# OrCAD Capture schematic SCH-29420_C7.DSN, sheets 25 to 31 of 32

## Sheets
25 P22_HDMI_RX_TX: size A2
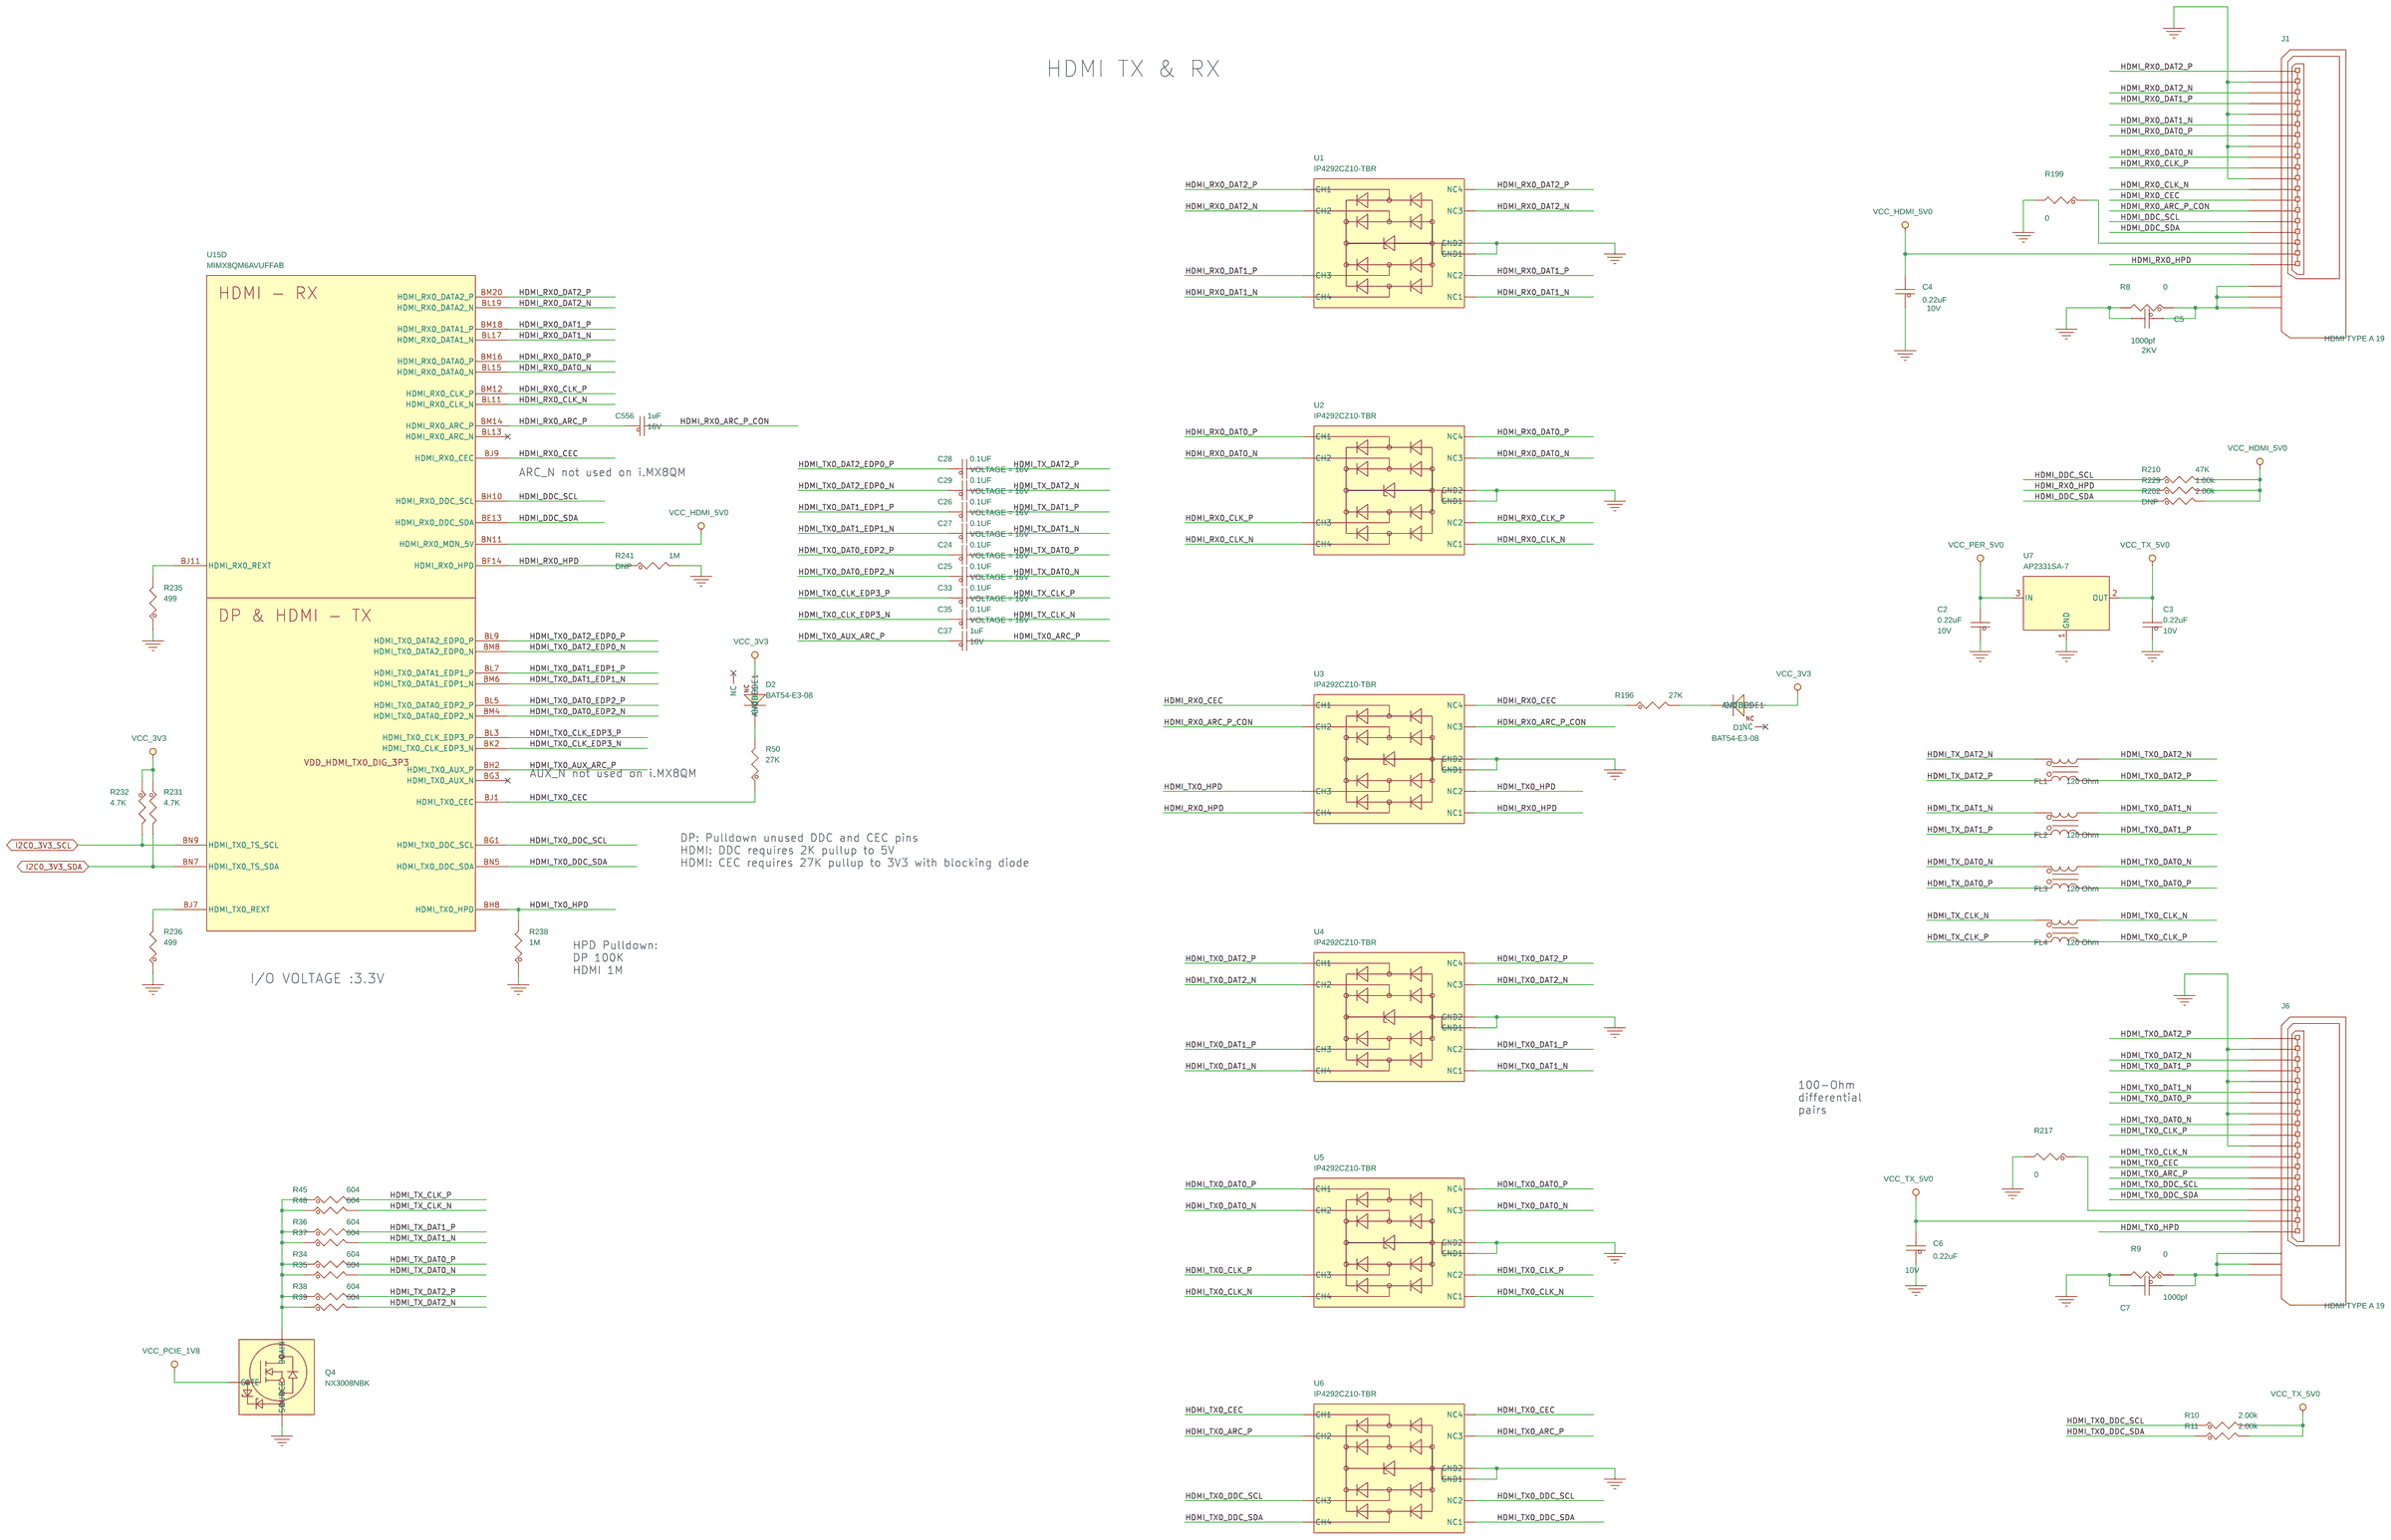
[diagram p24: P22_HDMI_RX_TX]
26 P25_WIFI_BLUETOOTH: size A2
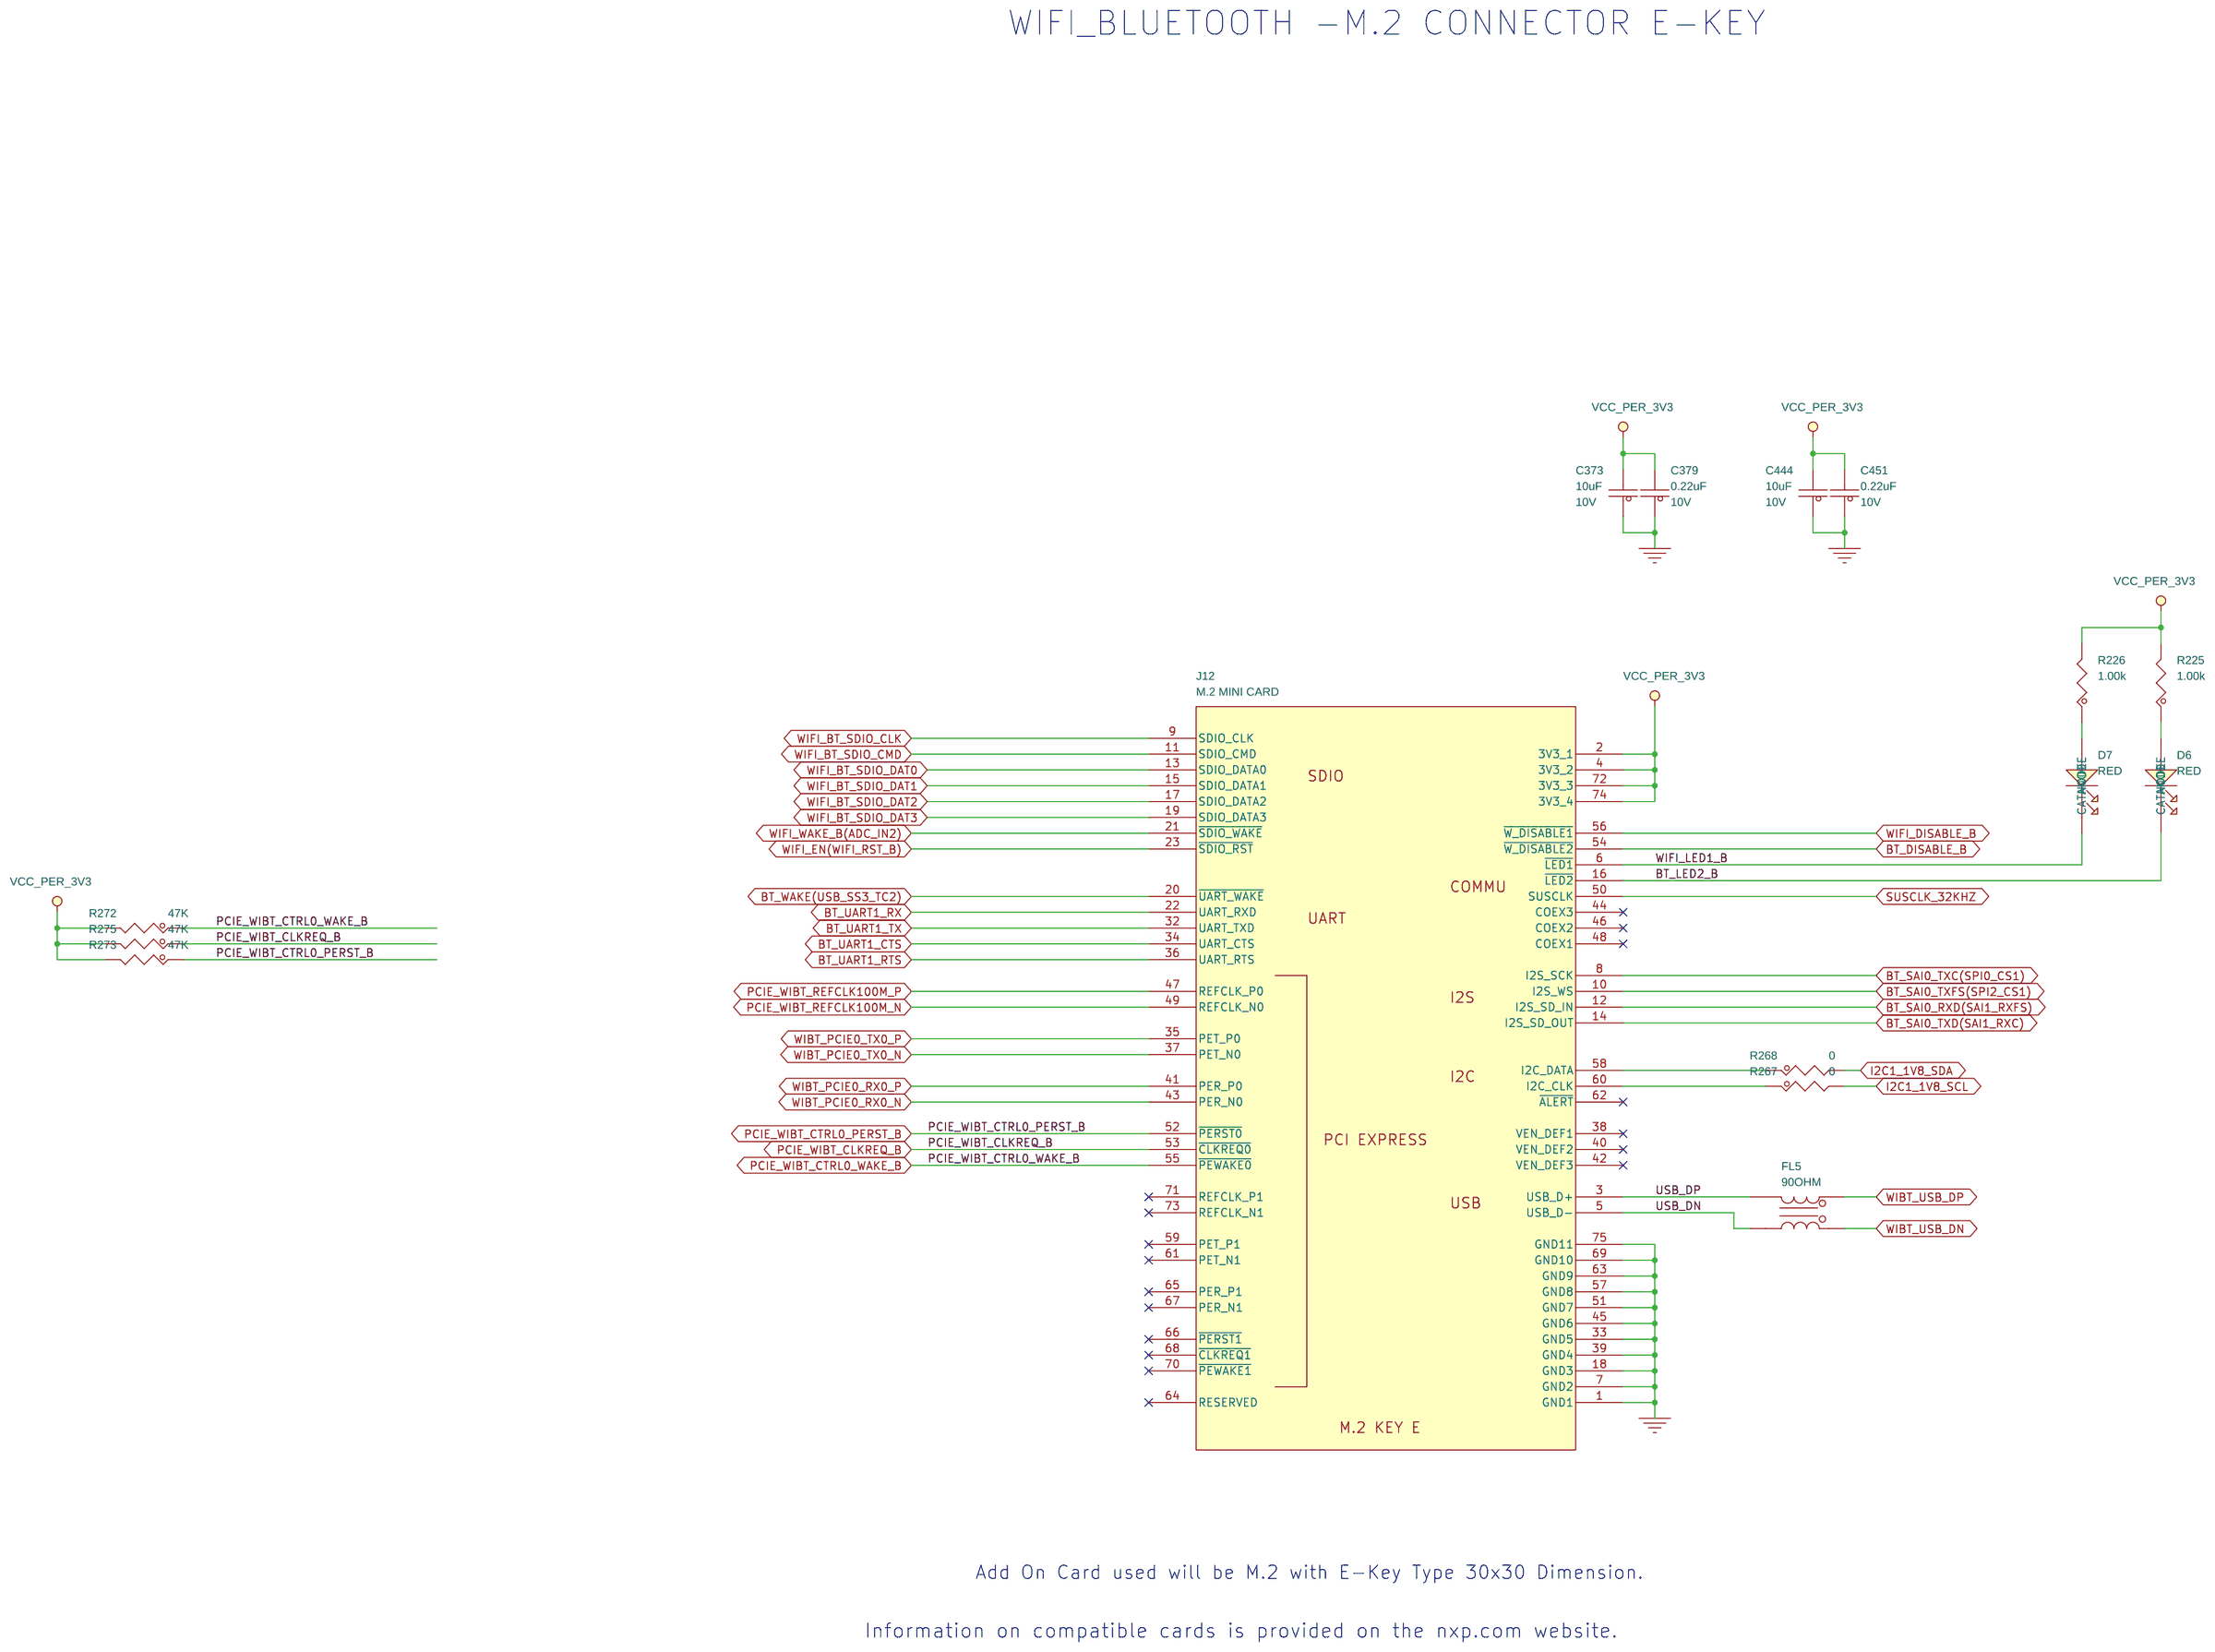
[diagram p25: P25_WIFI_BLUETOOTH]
27 P24_AUDIO CODEC_WM8960: size A2
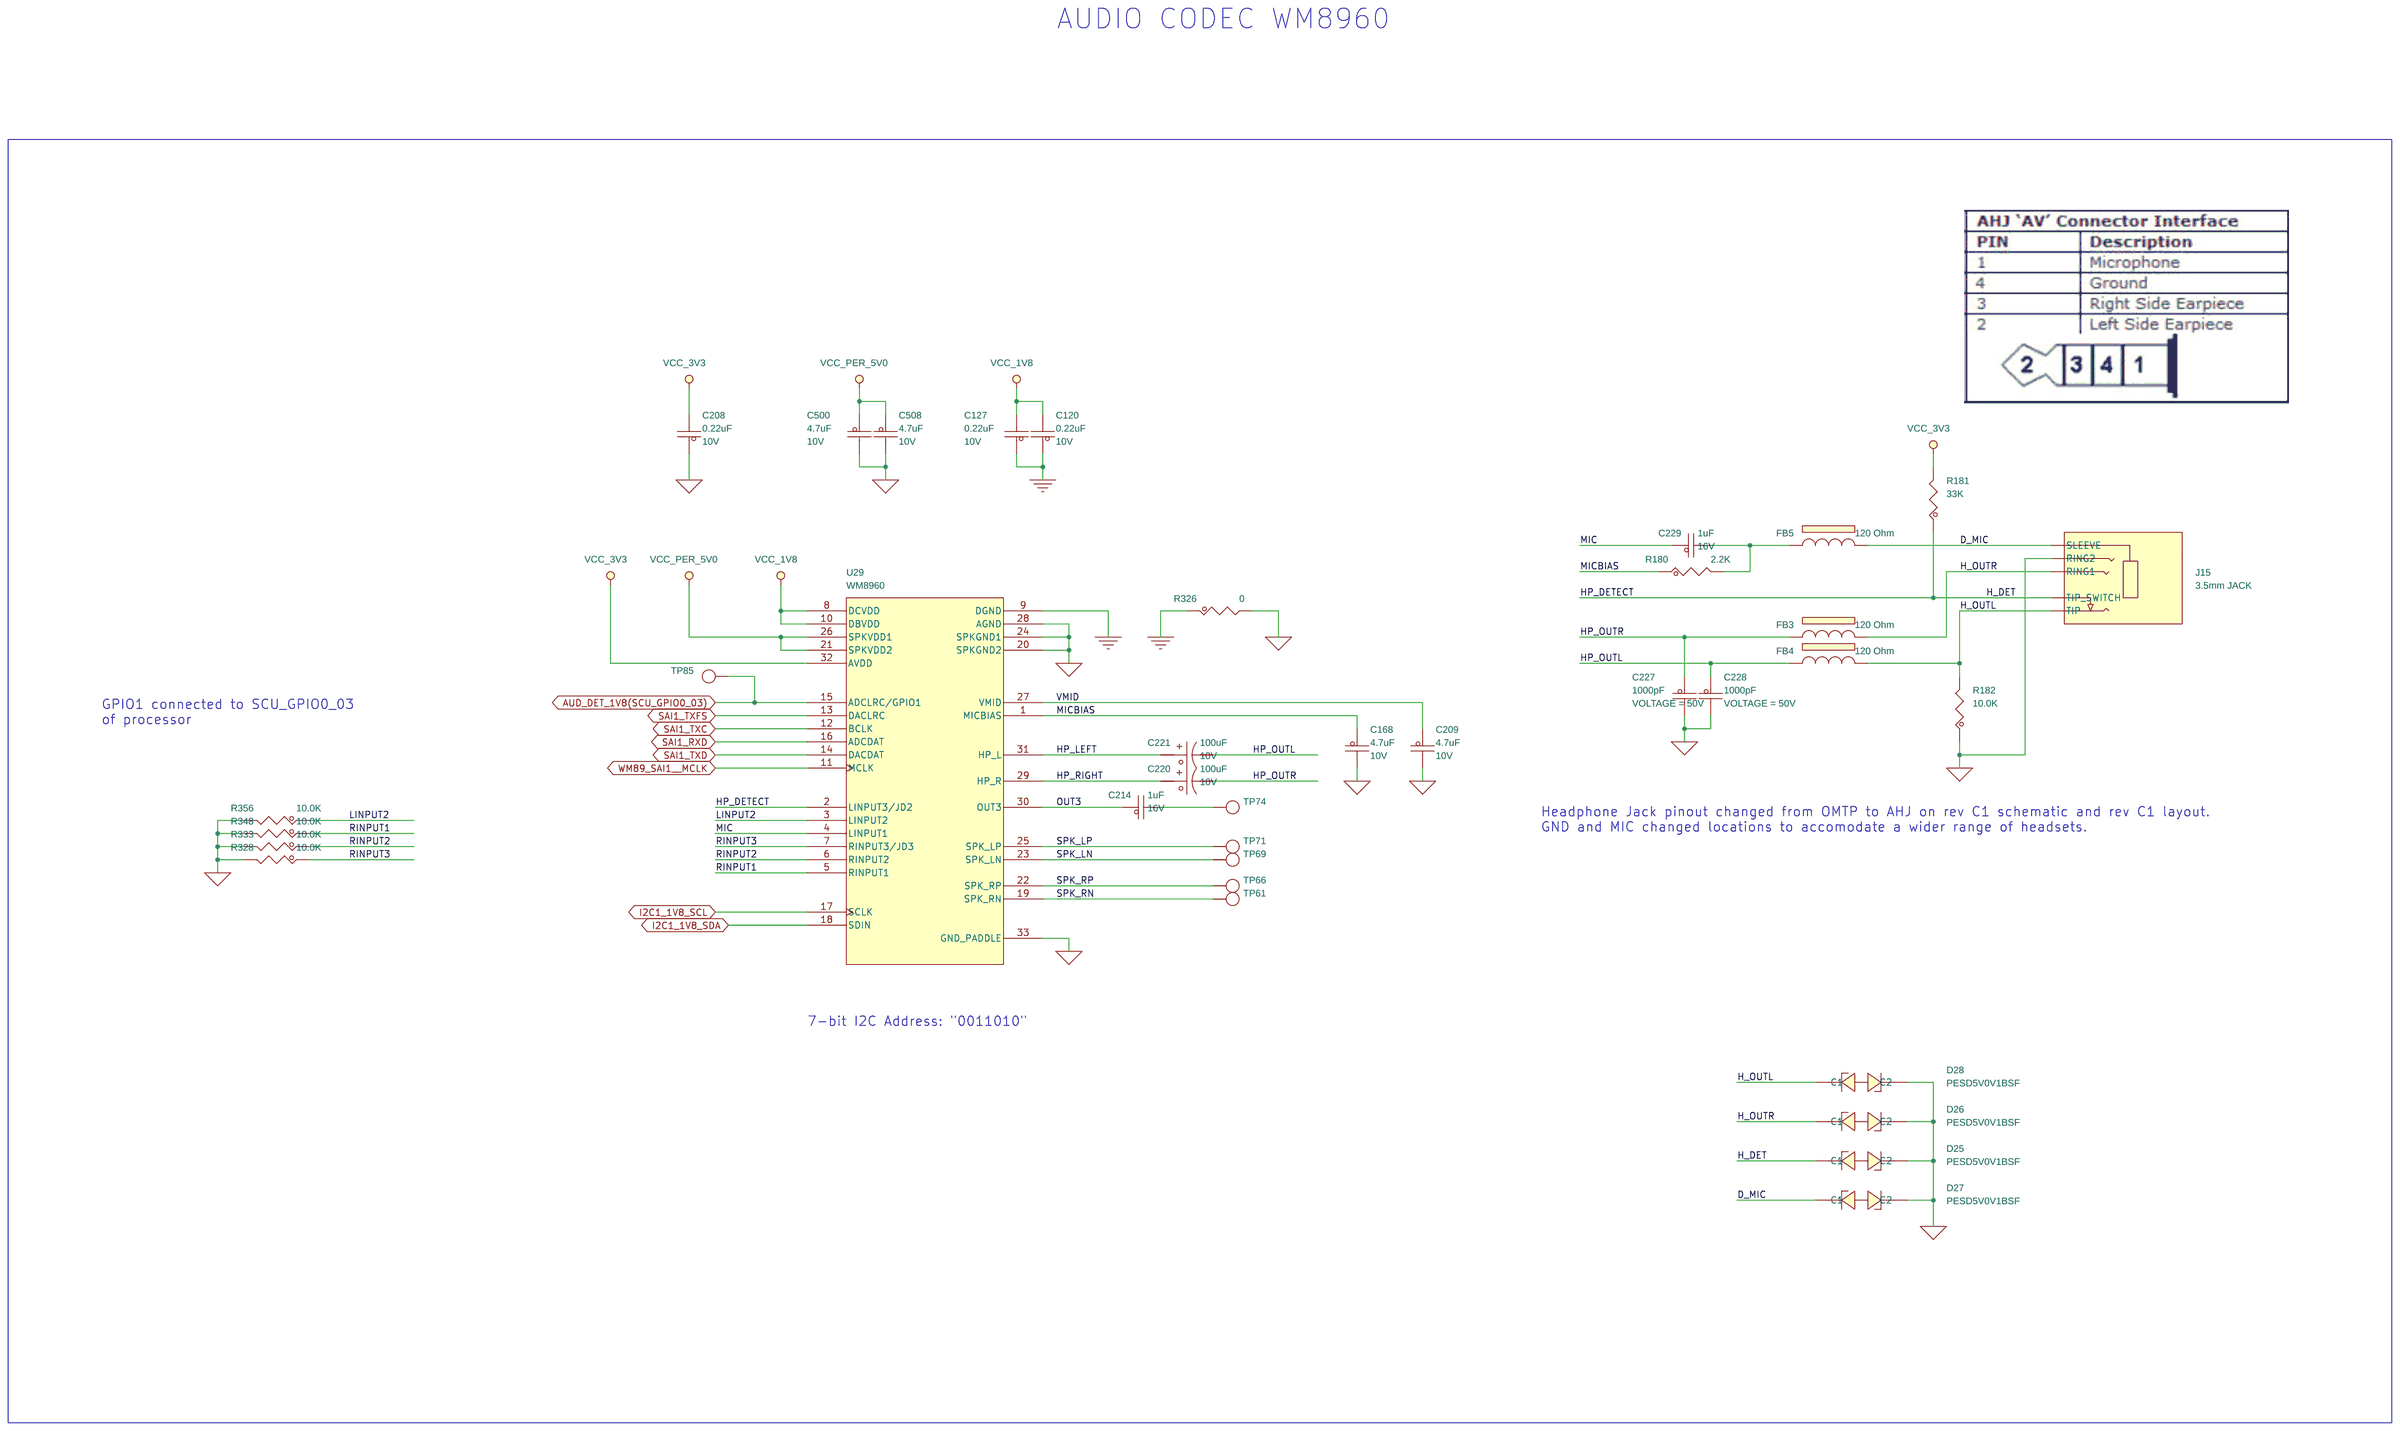
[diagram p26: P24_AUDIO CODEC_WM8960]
28 P26_SENSORS: size A2
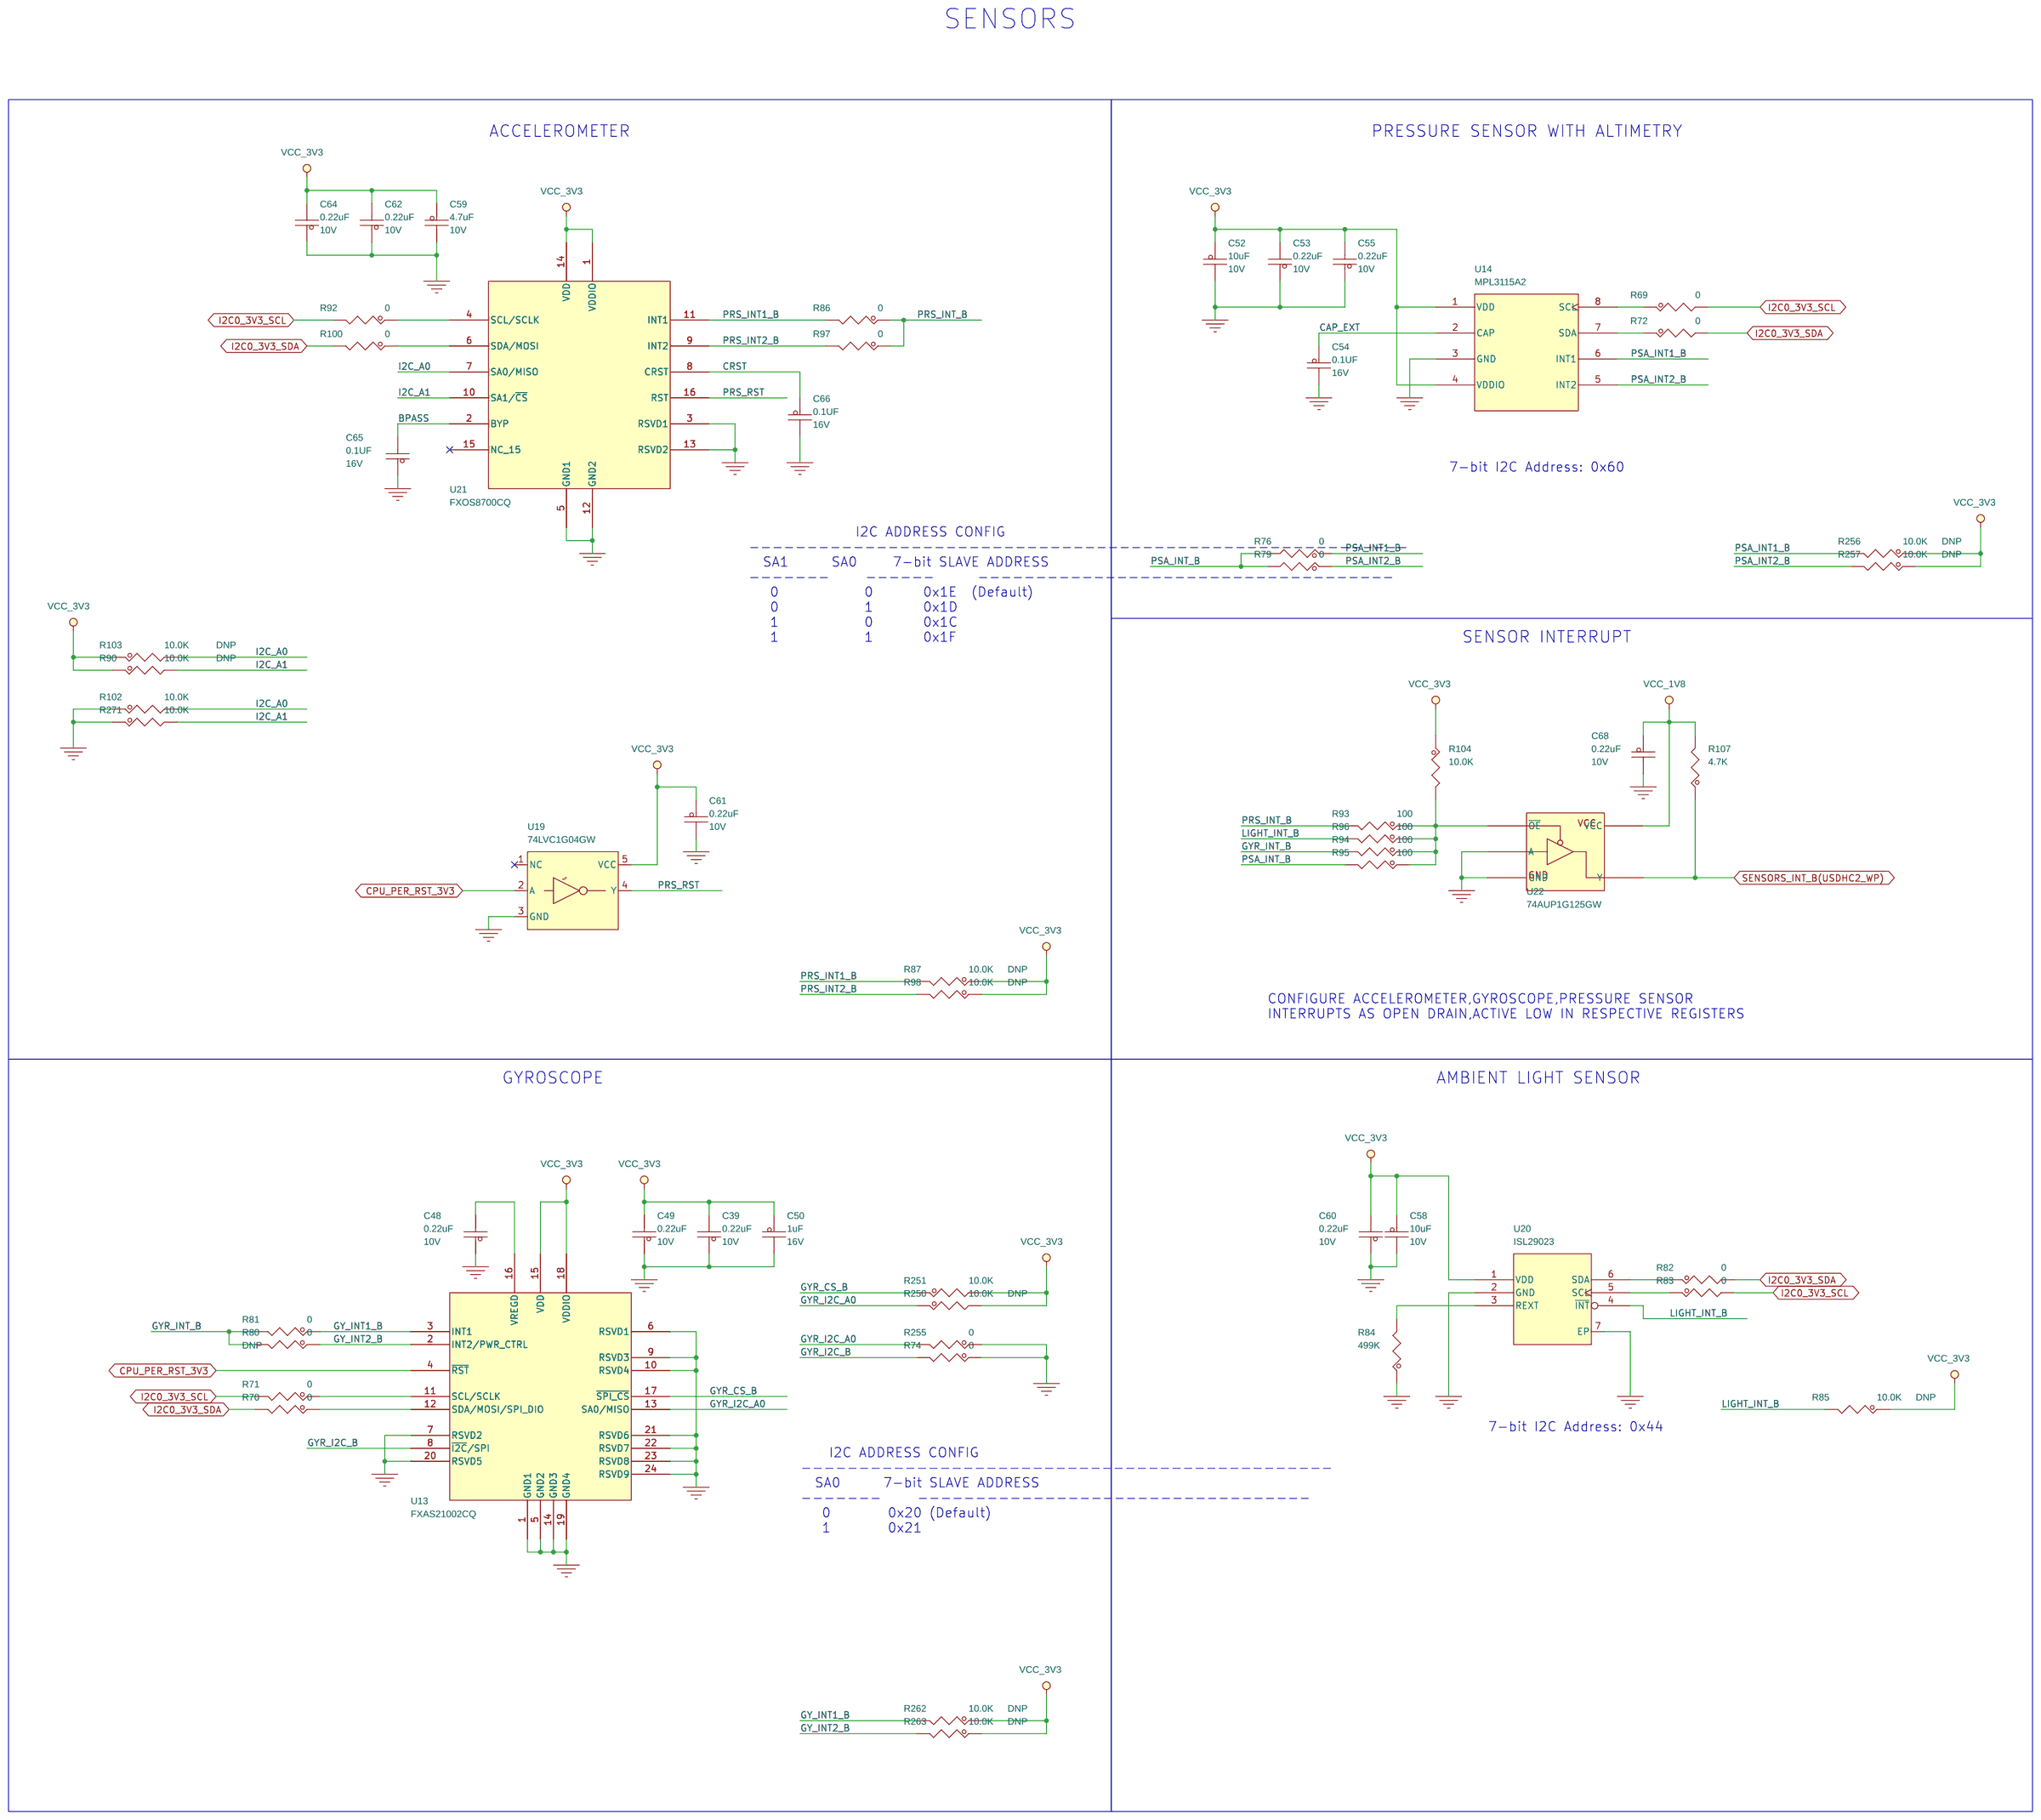
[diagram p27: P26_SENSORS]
29 P27_LVDS_CONNECTORS: size A2
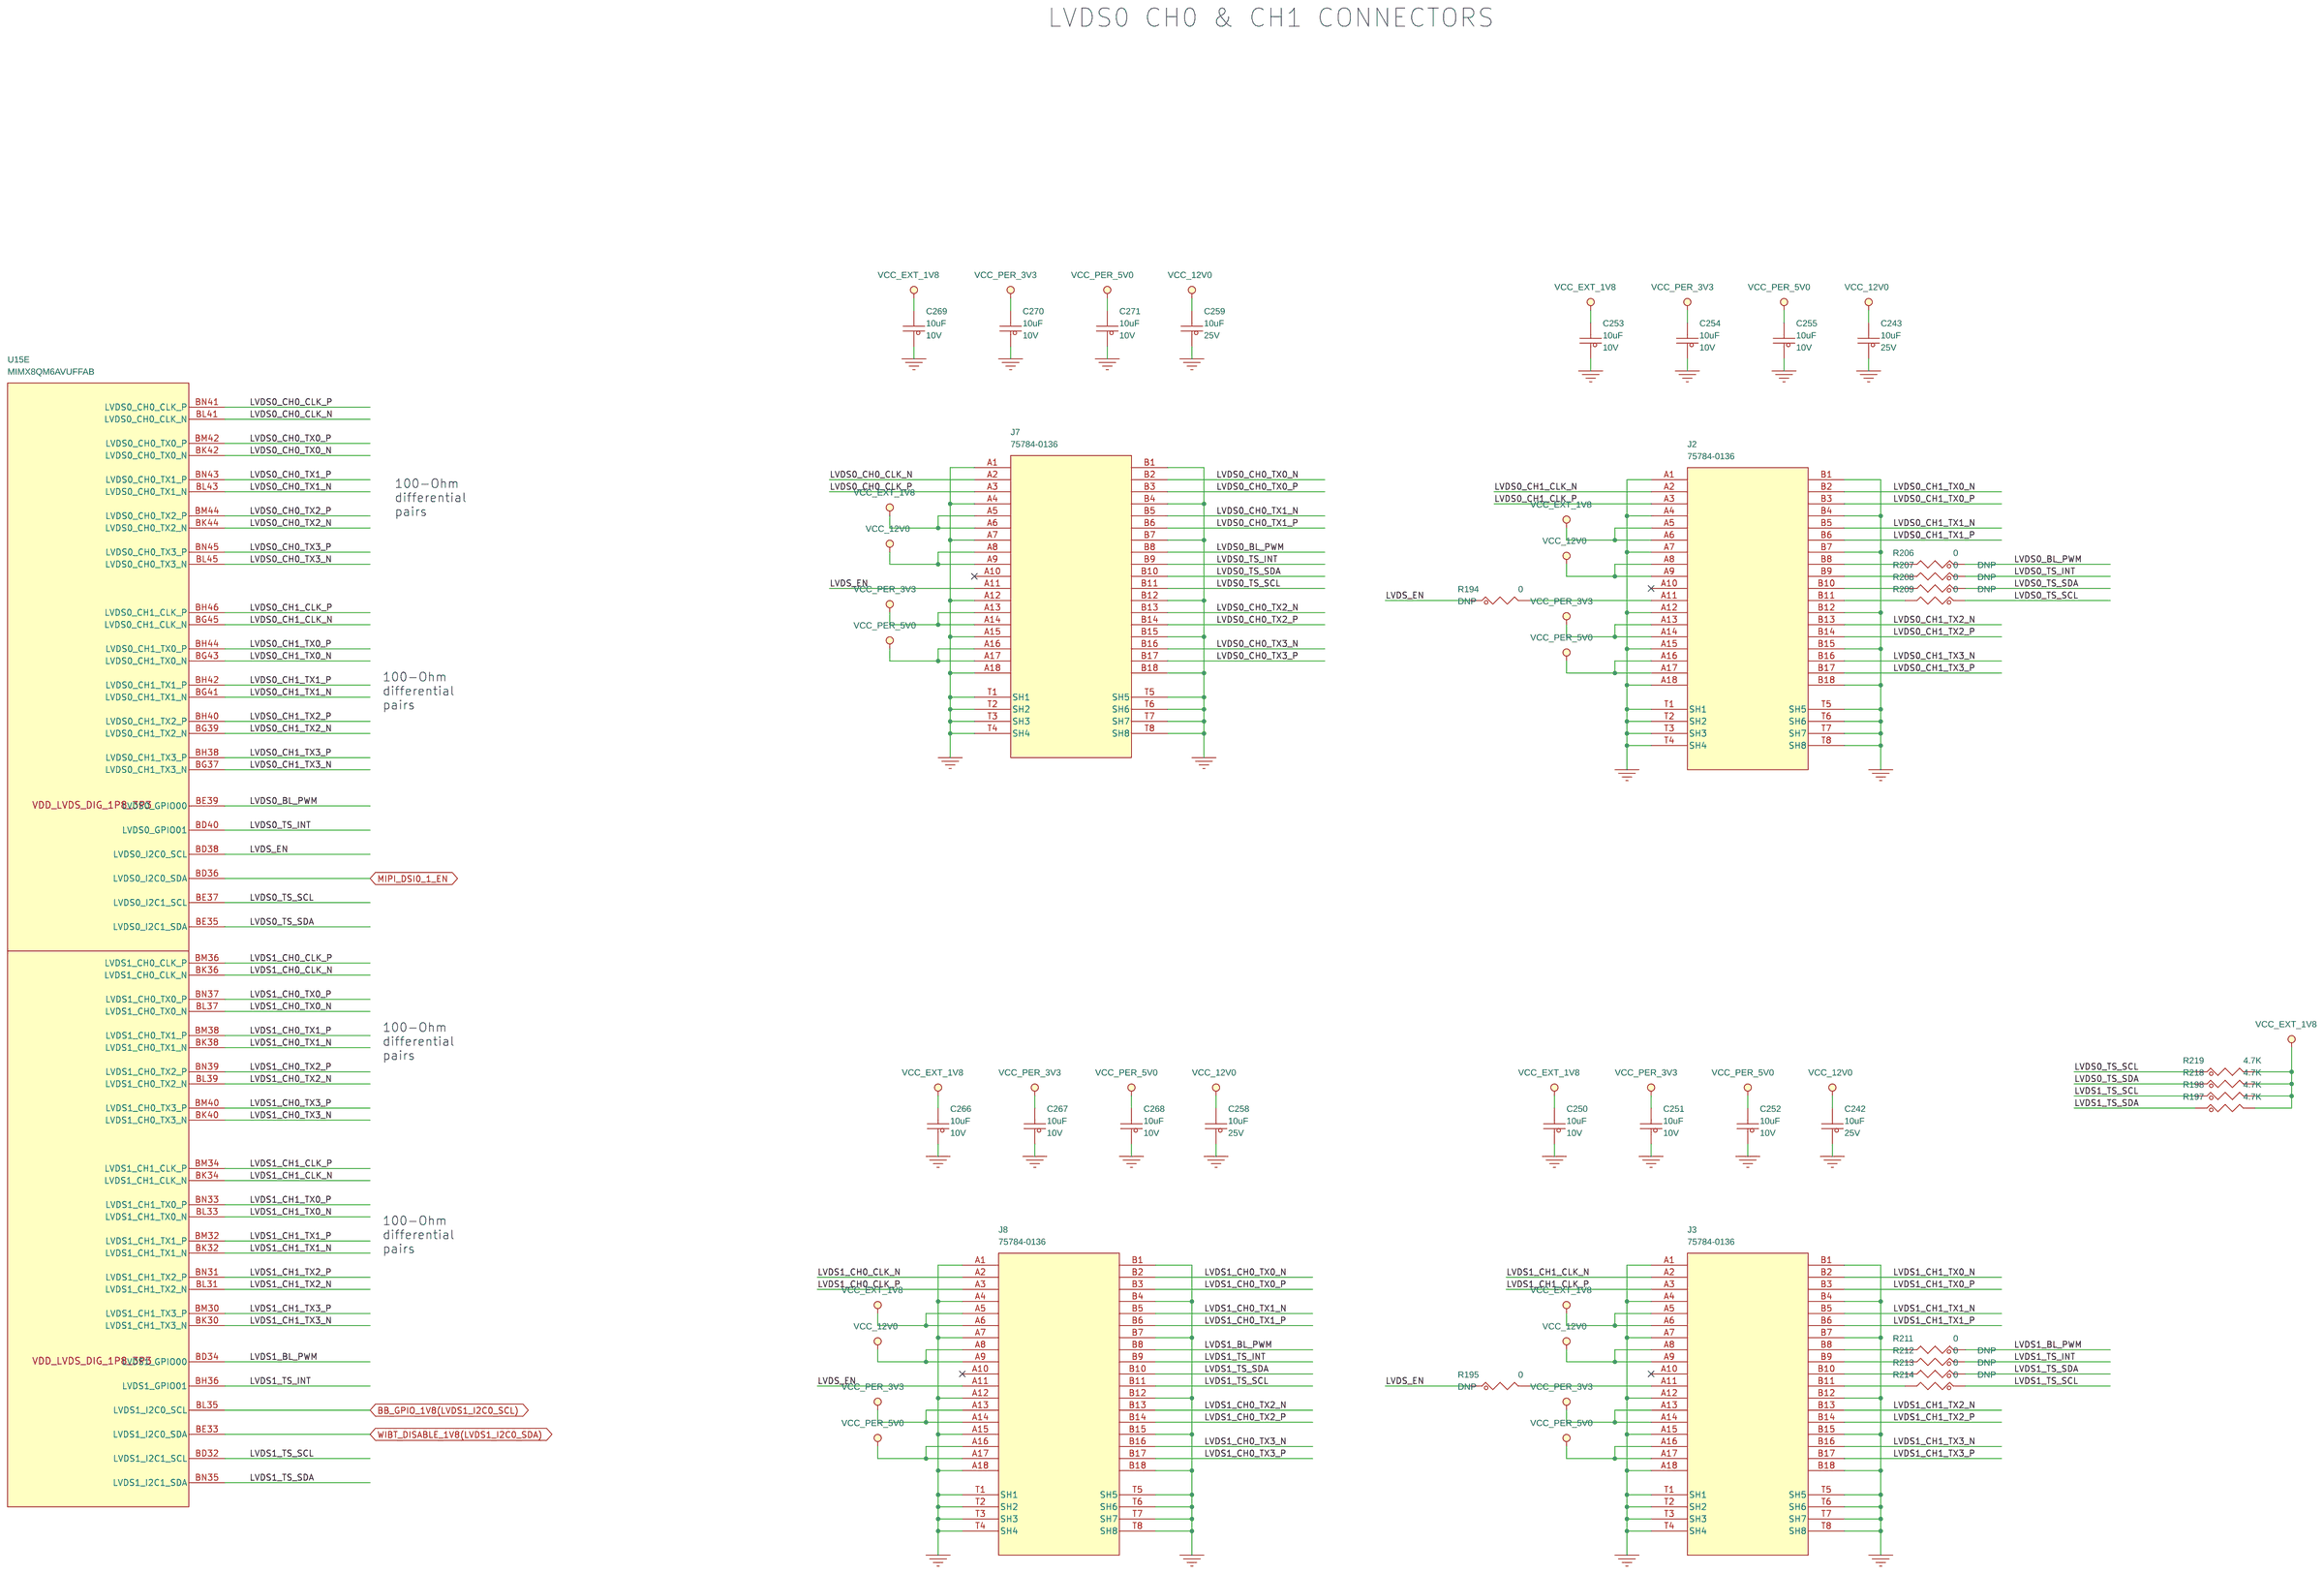
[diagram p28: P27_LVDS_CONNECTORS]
30 P28_MIPI_CSI_CONNECTORS: size A2
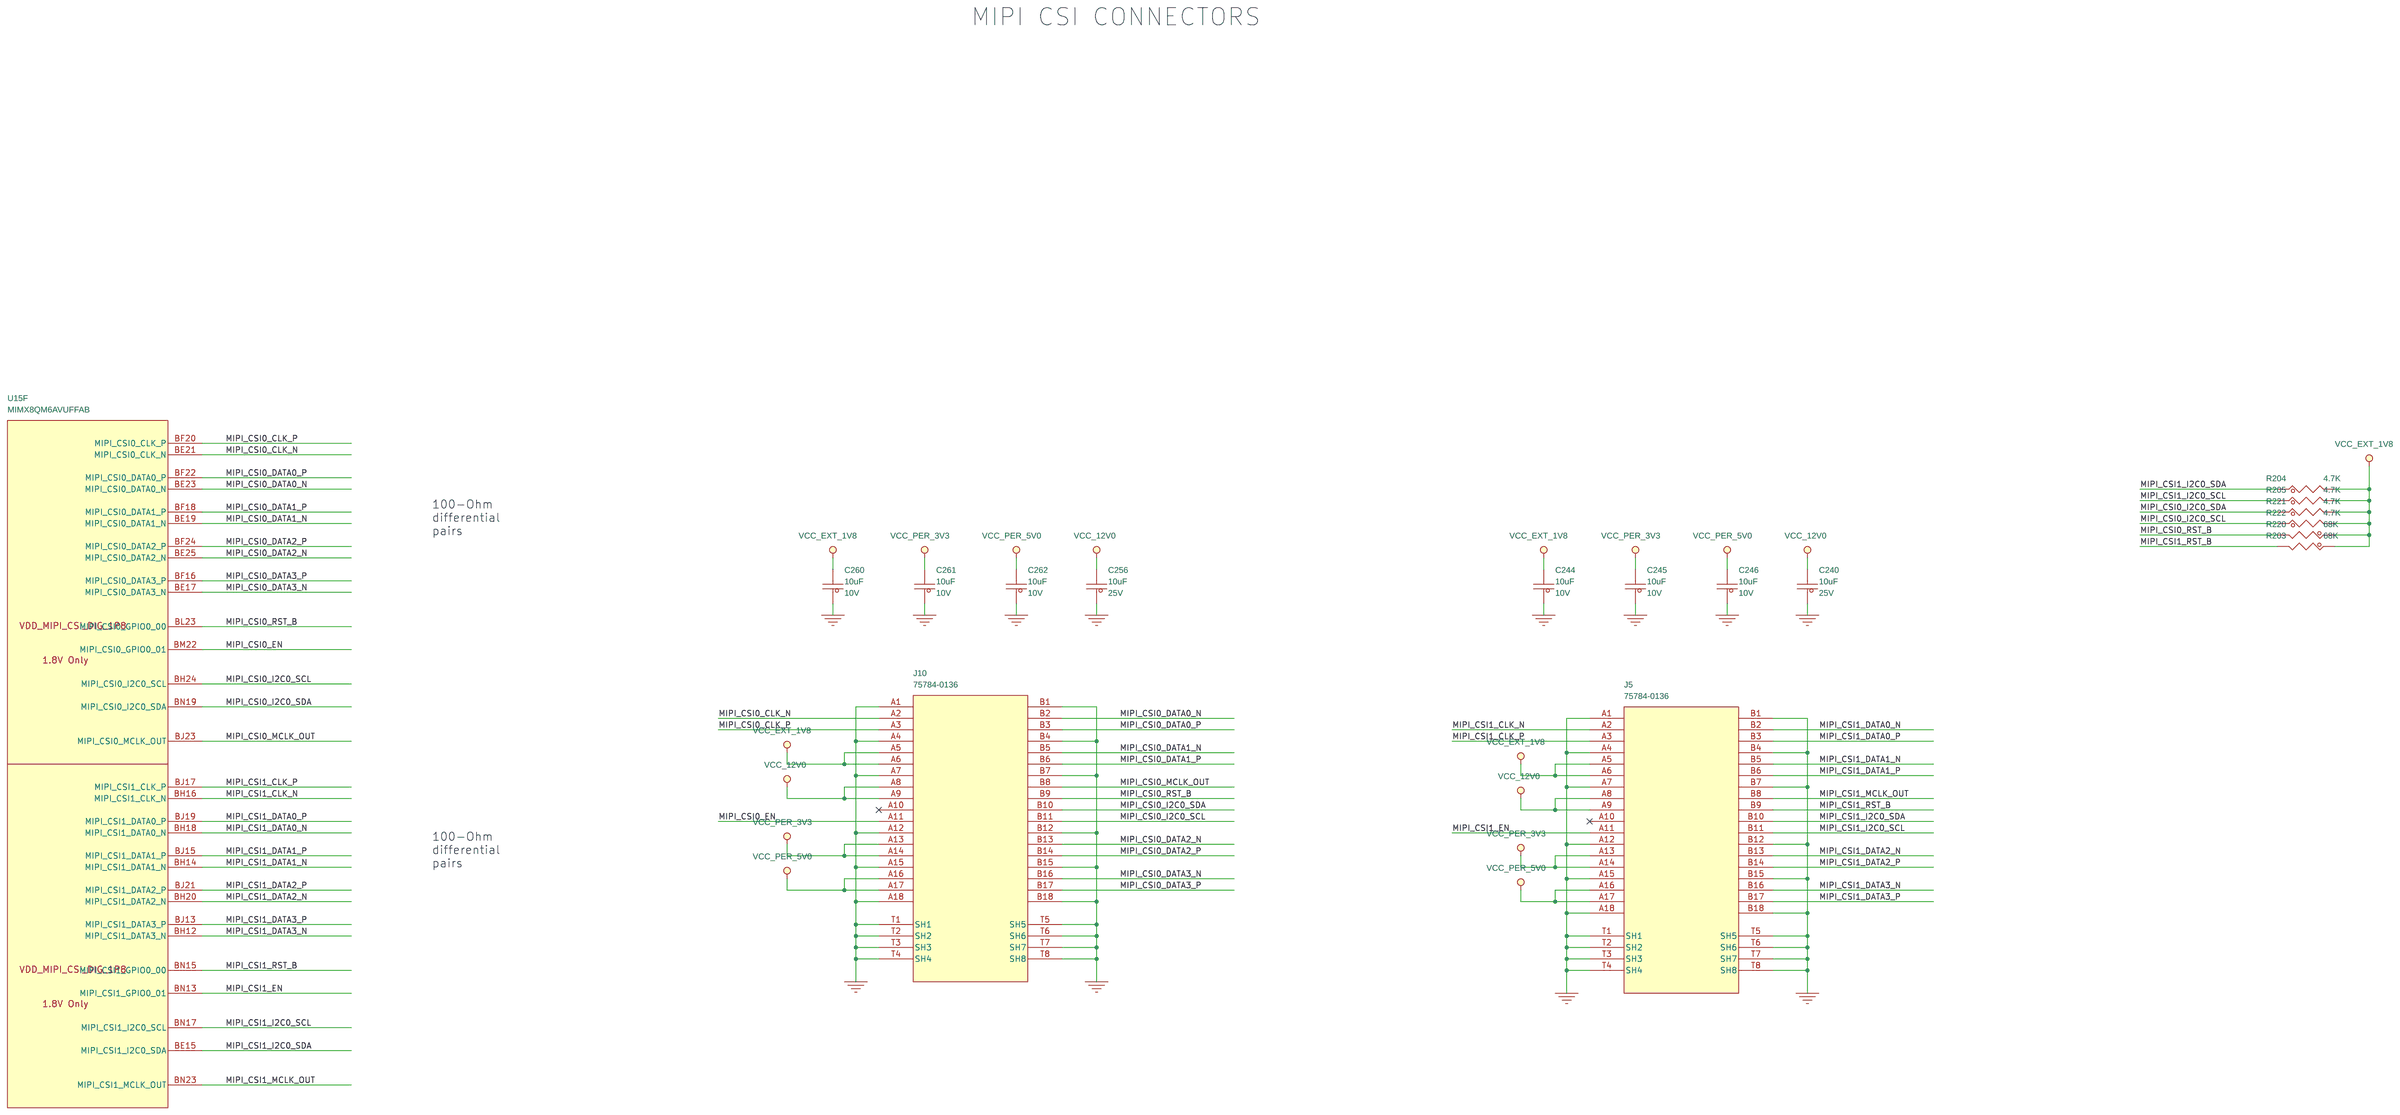
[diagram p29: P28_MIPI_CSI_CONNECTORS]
31 P31_LEVEL TRANSLATORS_DRIVERS: size A2
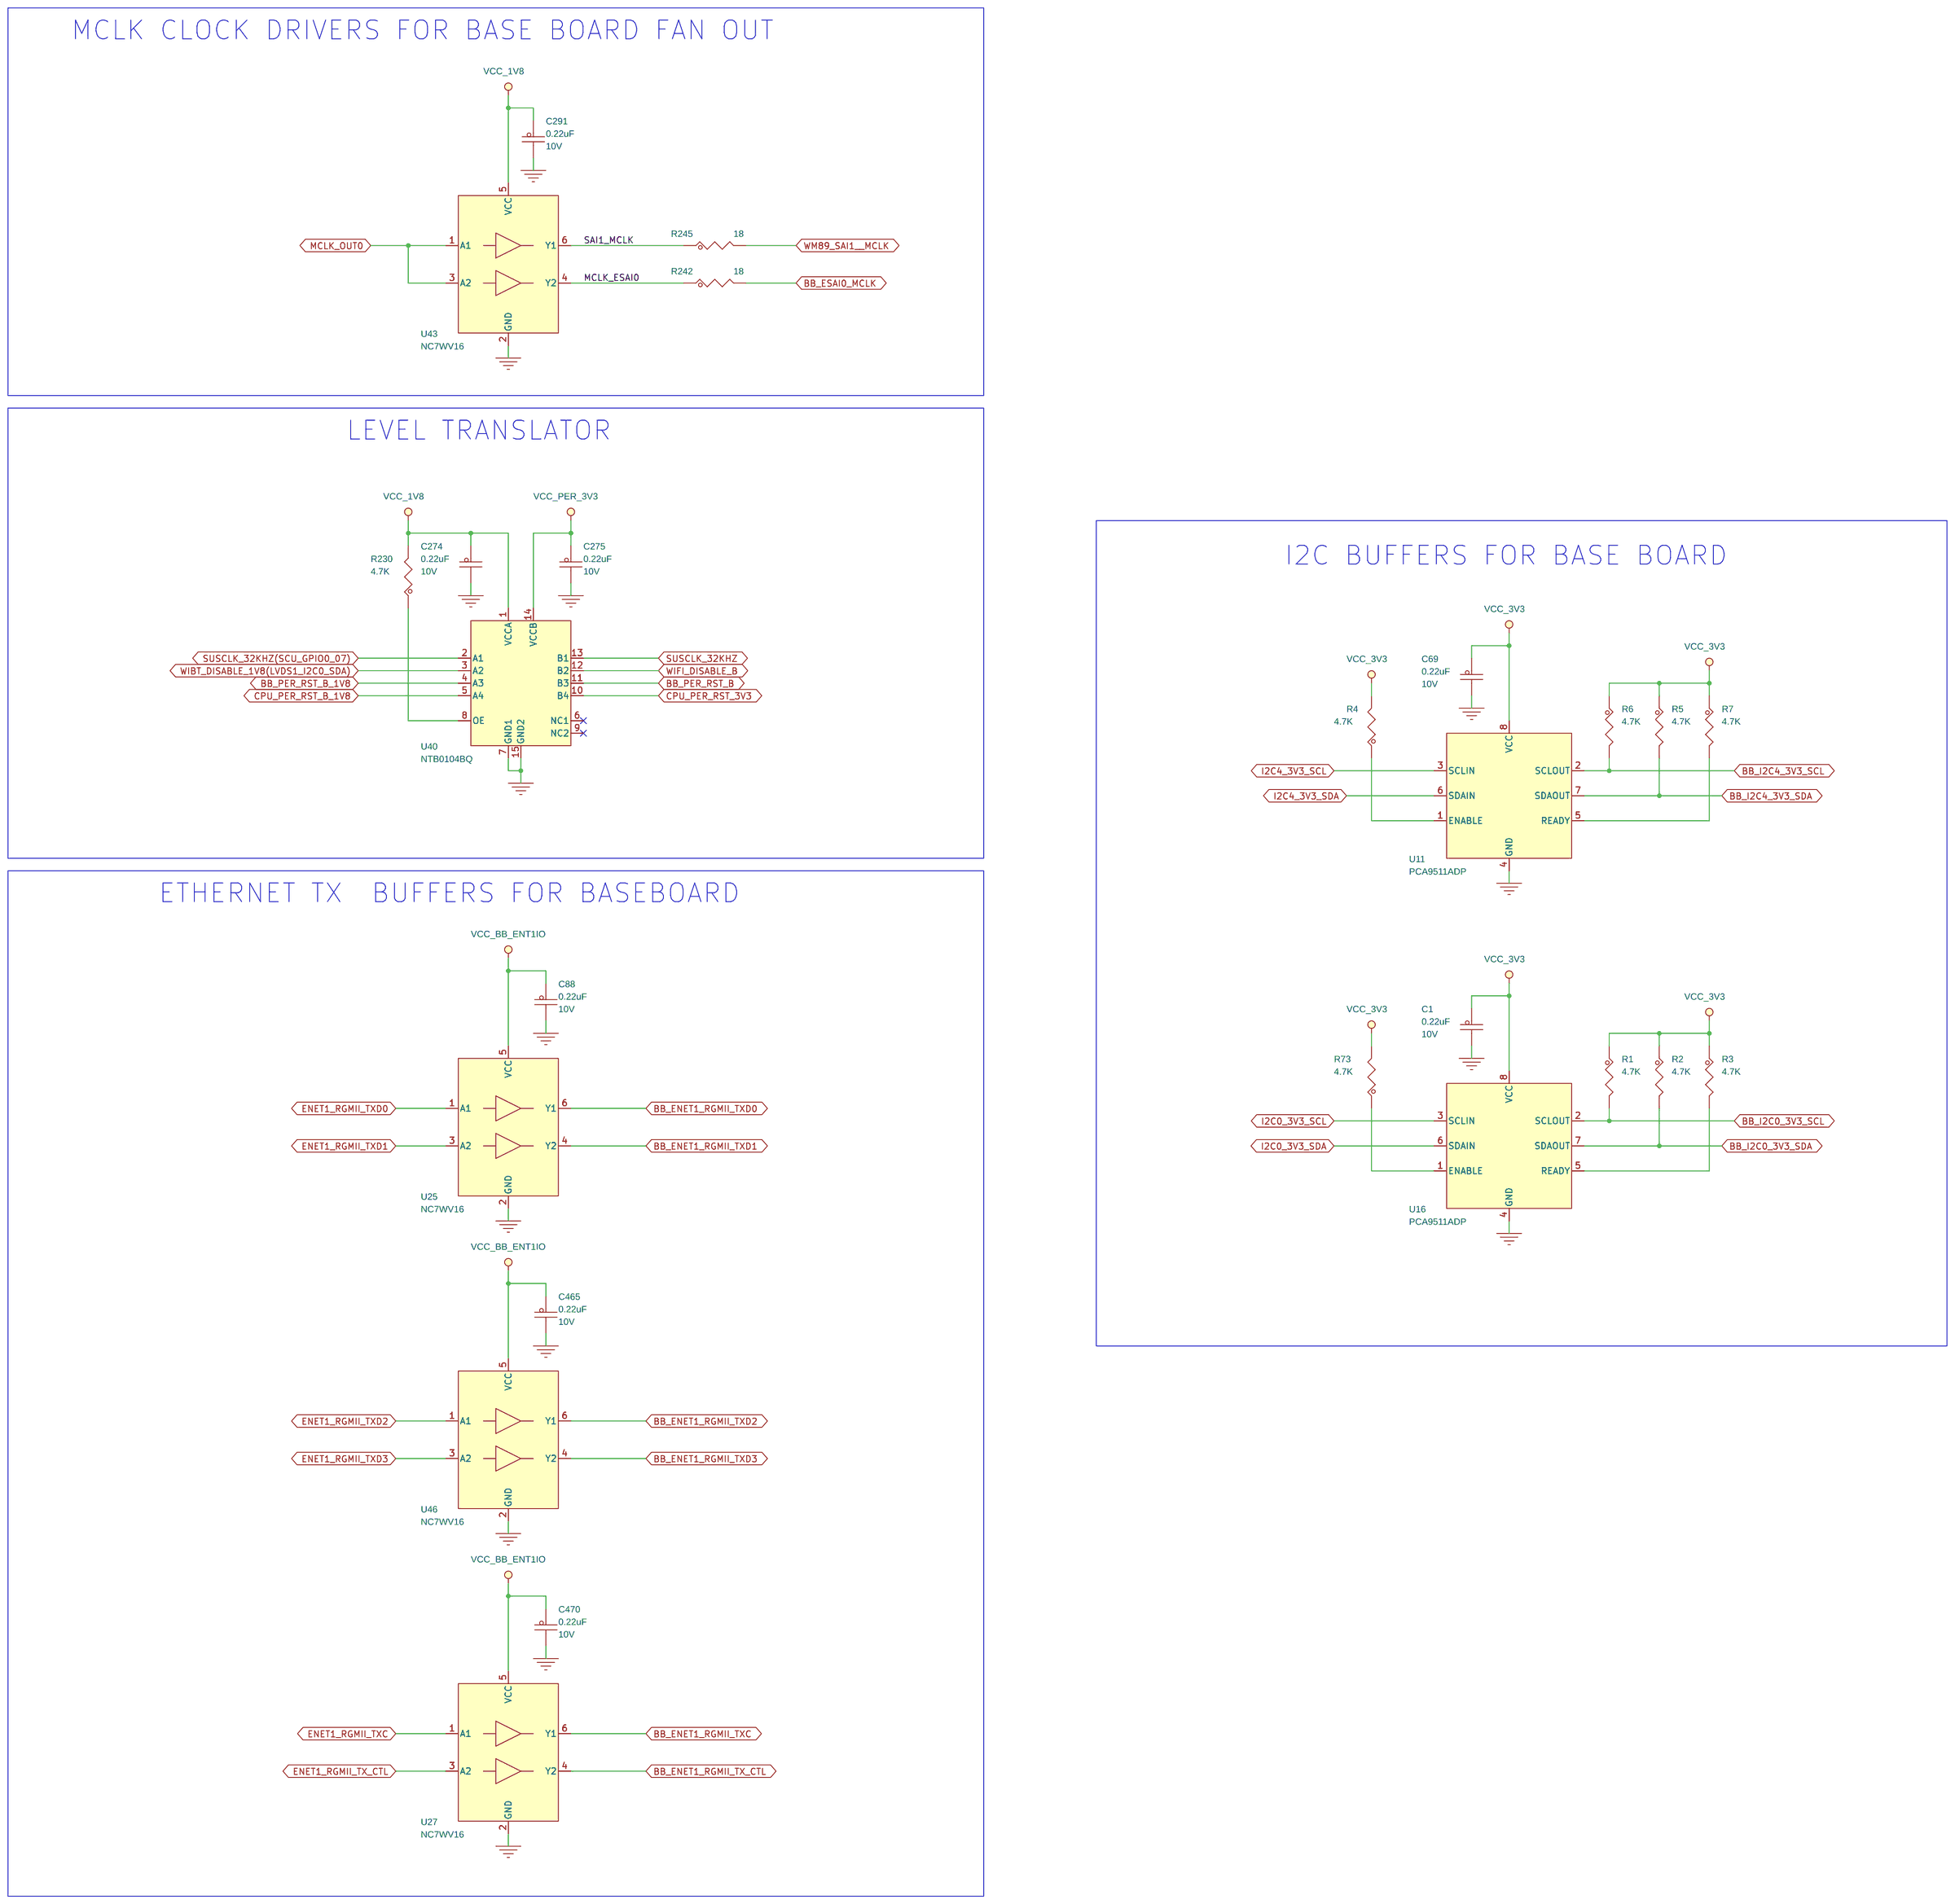
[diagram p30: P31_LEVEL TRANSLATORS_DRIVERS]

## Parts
sheet P20_USB3.x_TYPE_C
U15  MIMX8QM6AVUFFAB  [imx8_bga_1313]  (sections A,B,C,D,E,F,G,H,I,J,K,L,M,N,O,P,Q,R,S,T,U)
sheet P22_HDMI_RX_TX
C2  0.22uF  [CC0402_25]
C3  0.22uF  [CC0402_25]
C4  0.22uF  [CC0402_25]
C5  1000pf  [CC1210]
C6  0.22uF  [CC0402_25]
C7  1000pf  [CC1210]
C24  0.1UF  [0402_CC]
C25  0.1UF  [0402_CC]
C26  0.1UF  [0402_CC]
C27  0.1UF  [0402_CC]
C28  0.1UF  [0402_CC]
C29  0.1UF  [0402_CC]
C33  0.1UF  [0402_CC]
C35  0.1UF  [0402_CC]
C37  1uF  [0402_CC]
C556  1uF  [CC0402_25]
D1  BAT54-E3-08  [sot23_a]
D2  BAT54-E3-08  [sot23_a]
FL1  120 Ohm  [ind4_choke_0805]
FL2  120 Ohm  [ind4_choke_0805]
FL3  120 Ohm  [ind4_choke_0805]
FL4  120 Ohm  [ind4_choke_0805]
J1  HDMI TYPE A 19  [con19_0p5_15p25x5p8mm]
J6  HDMI TYPE A 19  [con19_0p5_15p25x5p8mm]
Q4  NX3008NBK  [SOT23_A]
R8  0  [RC0402_25]
R9  0  [RC0402_25]
R10  2.00k  [RC0402_25]
R11  2.00k  [RC0402_25]
R34  604  [0402_CC]
R35  604  [0402_CC]
R36  604  [0402_CC]
R37  604  [0402_CC]
R38  604  [0402_CC]
R39  604  [0402_CC]
R45  604  [0402_CC]
R48  604  [0402_CC]
R50  27K  [RC0402_25]
R196  27K  [RC0402_25]
R199  0  [RC0402_25]
R202  2.00k  [RC0402_25]
R210  47K  [RC0402_25]
R217  0  [RC0402_25]
R229  1.00k  [RC0402_25]
R231  4.7K  [RC0402_25]
R232  4.7K  [RC0402_25]
R235  499  [RC0402_25]
R236  499  [RC0402_25]
R238  1M  [RC0402_25]
R241  1M  [RC0402_25]
U1  IP4292CZ10-TBR  [xson10_0p5_1p1x2p6mm]
U2  IP4292CZ10-TBR  [xson10_0p5_1p1x2p6mm]
U3  IP4292CZ10-TBR  [xson10_0p5_1p1x2p6mm]
U4  IP4292CZ10-TBR  [xson10_0p5_1p1x2p6mm]
U5  IP4292CZ10-TBR  [xson10_0p5_1p1x2p6mm]
U6  IP4292CZ10-TBR  [xson10_0p5_1p1x2p6mm]
U7  AP2331SA-7  [SOT-23]
sheet P24_AUDIO CODEC_WM8960
C120  0.22uF  [CC0402_25]
C127  0.22uF  [CC0402_25]
C168  4.7uF  [CC0402_25]
C208  0.22uF  [CC0402_25]
C209  4.7uF  [CC0402_25]
C214  1uF  [CC0402_25]
C220  100uF  [case_d_al]
C221  100uF  [case_d_al]
C227  1000pF  [CC0402_25]
C228  1000pF  [CC0402_25]
C229  1uF  [CC0402_25]
C500  4.7uF  [CC0402_25]
C508  4.7uF  [CC0402_25]
D25  PESD5V0V1BSF  [dsn0603-2]
D26  PESD5V0V1BSF  [dsn0603-2]
D27  PESD5V0V1BSF  [dsn0603-2]
D28  PESD5V0V1BSF  [dsn0603-2]
FB3  120 Ohm  [IND_0402]
FB4  120 Ohm  [IND_0402]
FB5  120 Ohm  [IND_0402]
J15  3.5mm JACK  [con_audjack_4f_2p8_sm_ra]
R180  2.2K  [RC0402_25]
R181  33K  [RC0402_25]
R182  10.0K  [RC0402_25]
R326  0  [RC0402_25]
R328  10.0K  [RC0402_25]
R333  10.0K  [RC0402_25]
R348  10.0K  [RC0402_25]
R356  10.0K  [RC0402_25]
TP61  TPAD_050  [TPAD_050]
TP66  TPAD_050  [TPAD_050]
TP69  TPAD_050  [TPAD_050]
TP71  TPAD_050  [TPAD_050]
TP74  TPAD_050  [TPAD_050]
TP85  TPAD_050  [TPAD_050]
U29  WM8960  [qfn32_s142ep]
sheet P25_WIFI_BLUETOOTH
C373  10uF  [CC0603_OV]
C379  0.22uF  [CC0402_25]
C444  10uF  [CC0603_OV]
C451  0.22uF  [CC0402_25]
D6  RED  [LED_0603]
D7  RED  [LED_0603]
FL5  90OHM  [ind4_choke_0805]
J12  M.2 MINI CARD  [con_67_0p5_22x7p75_ra]
R225  1.00k  [RC0402_25]
R226  1.00k  [RC0402_25]
R267  0  [RC0402_25]
R268  0  [RC0402_25]
R272  47K  [RC0402_25]
R273  47K  [RC0402_25]
R275  47K  [RC0402_25]
sheet P26_SENSORS
C39  0.22uF  [CC0402_25]
C48  0.22uF  [CC0402_25]
C49  0.22uF  [CC0402_25]
C50  1uF  [CC0402_25]
C52  10uF  [CC0603_OV]
C53  0.22uF  [CC0402_25]
C54  0.1UF  [CC0402_25]
C55  0.22uF  [CC0402_25]
C58  10uF  [CC0603_OV]
C59  4.7uF  [CC0402_25]
C60  0.22uF  [CC0402_25]
C61  0.22uF  [CC0402_25]
C62  0.22uF  [CC0402_25]
C64  0.22uF  [CC0402_25]
C65  0.1UF  [CC0402_25]
C66  0.1UF  [CC0402_25]
C68  0.22uF  [CC0402_25]
R69  0  [RC0402_25]
R70  0  [RC0402_25]
R71  0  [RC0402_25]
R72  0  [RC0402_25]
R74  0  [RC0402_25]
R76  0  [RC0402_25]
R79  0  [RC0402_25]
R80  0  [RC0402_25]
R81  0  [RC0402_25]
R82  0  [RC0402_25]
R83  0  [RC0402_25]
R84  499K  [RC0402_25]
R85  10.0K  [RC0402_25]
R86  0  [RC0402_25]
R87  10.0K  [RC0402_25]
R90  10.0K  [RC0402_25]
R92  0  [RC0402_25]
R93  100  [RC0402_25]
R94  100  [RC0402_25]
R95  100  [RC0402_25]
R96  100  [RC0402_25]
R97  0  [RC0402_25]
R98  10.0K  [RC0402_25]
R100  0  [RC0402_25]
R102  10.0K  [RC0402_25]
R103  10.0K  [RC0402_25]
R104  10.0K  [RC0402_25]
R107  4.7K  [RC0402_25]
R250  10.0K  [RC0402_25]
R251  10.0K  [RC0402_25]
R255  0  [RC0402_25]
R256  10.0K  [RC0402_25]
R257  10.0K  [RC0402_25]
R262  10.0K  [RC0402_25]
R263  10.0K  [RC0402_25]
R271  10.0K  [RC0402_25]
U13  FXAS21002CQ  [QFN24_0P5_4X4_ASYM_EXP]
U14  MPL3115A2  [LGA8_1P25_3X5_0P5]
U19  74LVC1G04GW  [sc70-5]
U20  ISL29023  [dfn_6_0p65_2p1x2]
U21  FXOS8700CQ  [QFN5X3_0P5_3X3]
U22  74AUP1G125GW  [SC70-5]
sheet P27_LVDS_CONNECTORS
C242  10uF  [CC0603_OV]
C243  10uF  [CC0603_OV]
C250  10uF  [CC0603_OV]
C251  10uF  [CC0603_OV]
C252  10uF  [CC0603_OV]
C253  10uF  [CC0603_OV]
C254  10uF  [CC0603_OV]
C255  10uF  [CC0603_OV]
C258  10uF  [CC0603_OV]
C259  10uF  [CC0603_OV]
C266  10uF  [CC0603_OV]
C267  10uF  [CC0603_OV]
C268  10uF  [CC0603_OV]
C269  10uF  [CC0603_OV]
C270  10uF  [CC0603_OV]
C271  10uF  [CC0603_OV]
J2  75784-0136  [con_36_0p8_th]
J3  75784-0136  [con_36_0p8_th]
J7  75784-0136  [con_36_0p8_th]
J8  75784-0136  [con_36_0p8_th]
R194  0  [RC0402_25]
R195  0  [RC0402_25]
R197  4.7K  [RC0402_25]
R198  4.7K  [RC0402_25]
R206  0  [RC0402_25]
R207  0  [RC0402_25]
R208  0  [RC0402_25]
R209  0  [RC0402_25]
R211  0  [RC0402_25]
R212  0  [RC0402_25]
R213  0  [RC0402_25]
R214  0  [RC0402_25]
R218  4.7K  [RC0402_25]
R219  4.7K  [RC0402_25]
sheet P28_MIPI_CSI_CONNECTORS
C240  10uF  [CC0603_OV]
C244  10uF  [CC0603_OV]
C245  10uF  [CC0603_OV]
C246  10uF  [CC0603_OV]
C256  10uF  [CC0603_OV]
C260  10uF  [CC0603_OV]
C261  10uF  [CC0603_OV]
C262  10uF  [CC0603_OV]
J5  75784-0136  [con_36_0p8_th]
J10  75784-0136  [con_36_0p8_th]
R203  68K  [RC0402_25]
R204  4.7K  [RC0402_25]
R205  4.7K  [RC0402_25]
R220  68K  [RC0402_25]
R221  4.7K  [RC0402_25]
R222  4.7K  [RC0402_25]
sheet P31_LEVEL TRANSLATORS_DRIVERS
C1  0.22uF  [CC0402_25]
C69  0.22uF  [CC0402_25]
C88  0.22uF  [CC0402_25]
C274  0.22uF  [CC0402_25]
C275  0.22uF  [CC0402_25]
C291  0.22uF  [CC0402_25]
C465  0.22uF  [CC0402_25]
C470  0.22uF  [CC0402_25]
R1  4.7K  [RC0402_25]
R2  4.7K  [RC0402_25]
R3  4.7K  [RC0402_25]
R4  4.7K  [RC0402_25]
R5  4.7K  [RC0402_25]
R6  4.7K  [RC0402_25]
R7  4.7K  [RC0402_25]
R73  4.7K  [RC0402_25]
R230  4.7K  [RC0402_25]
R242  18  [RC0402_25]
R245  18  [RC0402_25]
U11  PCA9511ADP  [TSSOP8_A]
U16  PCA9511ADP  [TSSOP8_A]
U25  NC7WV16  [sc70_6lead]
U27  NC7WV16  [sc70_6lead]
U40  NTB0104BQ  [dhvqfn14_3x2p5mm]
U43  NC7WV16  [sc70_6lead]
U46  NC7WV16  [sc70_6lead]

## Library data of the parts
U15 = PIMX8QM6AVUFFAB_BGA1313: IC CPU QUADMAX 2xA72 1.6GHz 4xA53 1.2GHZ M4 264MHZ FCPBGA1313; AGILE_PN: 330-77094; CAD_APPROVED: Yes; HEIGHT: 2.52MM; MFG_NAME01: NXP SEMICONDUCTORS; ROHS: Yes; Temp Range: -40°C to 125°C
C1-C4 C6 C39 C48 C49 C53 C55 C60-C62 C64 C68 C69 C88 C120 C127 C208 C274 C275 C291 C379 C451 C465 C470 = CAP_NP: CAP CER 0.22uF 10V 10% X7R AEC-Q200 0402; AGILE_PN: 150-79031; CAD_APPROVED: Yes; EN: 102-1-01816; FPLIST: CC0402_25,CC0402_HD,0402_CC; HEIGHT: 0.55MM; MFG_NAME01: TDK; MFG_PN01: CGA2B1X7R1A224K050BC; ROHS: Yes; TOL: 10%; Tolerance: 10%; VOLTAGE: 10V
C5 C7 = CAP_NP: CAP CER 1000PF 2KV 10% X7R 1210; AGILE_PN: 150-75027; CAD_APPROVED: Yes; EN: 102-1-01612; FPLIST: CC1210,1210_CC; HEIGHT: 1.7MM; MFG_NAME01: AVX; MFG_PN01: 1210GC102KAT1A; ROHS: Yes; TOL: 10%; Tolerance: 10%; VOLTAGE: 2KV
C24-C29 C33 C35 C54 C65 C66 = CAP_NP: CAP CER 0.1UF 16V 10% X7R 0402; AGILE_PN: 150-75182; CAD_APPROVED: Yes; EN: 102-1-01629; FPLIST: CC0402_25,CC0402_HD,0402_CC; HEIGHT: 0.635MM; MFG_NAME01: AVX; MFG_PN01: 0402YC104KAT2A; ROHS: Yes; TOL: 10%; Tolerance: 10%; VOLTAGE: 16V
C37 C50 C214 C229 C556 = CAP_NP: CAP CER 1uF 16V 10% X5R 0402; AGILE_PN: 150-79794; CAD_APPROVED: Yes; EN: 102-1-01641; FPLIST: CC0402_25,CC0402_HD,0402_CC; HEIGHT: 0.55MM; MFG_NAME01: NIC COMPONENTS CORP; MFG_PN01: NMC0402X5R105K16TRPF; ROHS: Yes; TOL: +/-10%; Tolerance: +/-10%; VOLTAGE: 16V
D1 D2 = DIODE_SOT23: DIODE SCH SGL 200mA 30V SOT23; AGILE_PN: 480-79858; CAD_APPROVED: Yes; EN: 106-2-00045; HEIGHT: 1.15MM; MFG_NAME01: VISHAY INTERTECHNOLOGY; ROHS: Yes
FL1-FL4 = DLW43: IND CHK 120 OHM@100MHZ 370MA 25% 0805; AGILE_PN: 180-77596; CAD_APPROVED: Yes; EN: 303-0-00108; HEIGHT: 1.4 MM; MFG_NAME01: Murata; MFG_PN01: DLW21SN121SQ2L; PART_TYPE: CHOKE; ROHS: Yes; TOL: 25%; Tolerance: 25%
J1 J6 = CON19_HDMI_VERT_CONNECT: CON 19 HDMI SKT SMT 0.5MM SP 75H AU; AGILE_PN: 211-80875; CAD_APPROVED: Yes; EN: 201-1-00854; HEIGHT: 9.75MM; MFG_NAME01: MOLEX; MFG_PN01: 476591100; Package Type: SMT; ROHS: Yes
Q4 = NMOS_NX3008NBK: TRAN NMOS PWR 30V 400mA AEC-Q101 SOT23; AGILE_PN: 480-79305; CAD_APPROVED: Yes; EN: 107-2-00226; FPLIST: SOT23_A,TO-236; HEIGHT: 1.1MM; MFG_NAME01: NEXPERIA; MFG_PN01: NX3008NBK,215; ROHS: Yes
R8 R9 R69-R72 R74 R76 R79 R81-R83 R86 R92 R97 R100 R199 R206 R211 R217 R255 R267 R268 R326 = RES: RES MF ZERO OHM 1/16W -- AEC-Q200 0402; AGILE_PN: 470-80742; CAD_APPROVED: Yes; EN: 101-1-00001; FPLIST: RC0402_25,RC0402_HD,0402_CC; HEIGHT: 0.45 MM; MFG_NAME01: VISHAY INTERTECHNOLOGY; MFG_PN01: CRCW04020000Z0ED; ROHS: Yes
R10 R11 = RES: RES MF 2K 1/16W 1% AEC-Q200 0402; AGILE_PN: 470-80507; CAD_APPROVED: Yes; EN: 101-1-00322; FPLIST: RC0402_25,RC0402_HD,0402_CC; HEIGHT: 0.4 MM; MFG_NAME01: KOA SPEER; MFG_PN01: RK73H1ETTP2001F; ROHS: Yes; TOL: 1%; Tolerance: 1%
R34-R39 R45 R48 = RES: RES MF 604 OHM 1/16W 1% 0402; AGILE_PN: 470-30815; CAD_APPROVED: Yes; EN: 101-1-00272; FPLIST: RC0402_25,RC0402_HD,0402_CC; HEIGHT: 0.40 MM; MFG_NAME01: SMEC; MFG_PN01: RC73A2Z6040FTF; ROHS: Yes; TOL: 1%; Tolerance: 1%
R50 R196 = RES: RES MF 27K 1/16W 5% 0402; AGILE_PN: 470-76069; CAD_APPROVED: Yes; EN: 101-1-02803; FPLIST: RC0402_25,RC0402_HD,0402_CC; HEIGHT: 0.40 MM; MFG_NAME01: VISHAY INTERTECHNOLOGY; MFG_PN01: CRCW040227K0JNED; ROHS: Yes; TOL: 5%; Tolerance: 5%
R202 = RES: RES MF 2K 1/16W 1% AEC-Q200 0402; AGILE_PN: 470-80507; ASSY_OPT: DNP; CAD_APPROVED: Yes; EN: 101-1-00322; FPLIST: RC0402_25,RC0402_HD,0402_CC; HEIGHT: 0.4 MM; MFG_NAME01: KOA SPEER; MFG_PN01: RK73H1ETTP2001F; ROHS: Yes; TOL: 1%; Tolerance: 1%
R210 R272 R273 R275 = RES: RES MF 47K 1/10W 1% AEC-Q200 0402; AGILE_PN: 470-81731; CAD_APPROVED: Yes; EN: 101-1-03402; FPLIST: RC0402_25,RC0402_HD,0402_CC; HEIGHT: 0.40 MM; MFG_NAME01: KOA SPEER; MFG_PN01: RK73H1ETTP4702F; ROHS: Yes; TOL: 1%; Temp_Range: -55C to +155C; Tolerance: 1%
R225 R226 R229 = RES: RES MF 1.00k Ohm 1/16W 1% AEC-Q200 0402; AGILE_PN: 470-80511; CAD_APPROVED: Yes; EN: 101-1-00293; FPLIST: RC0402_25,RC0402_HD,0402_CC; HEIGHT: 0.4 MM; MFG_NAME01: KOA SPEER; MFG_PN01: RK73H1ETTP1001F; ROHS: Yes; TOL: 1%; Tolerance: 1%
R1-R7 R73 R107 R197 R198 R204 R205 R218 R219 R221 R222 R230-R232 = RES: RES MF 4.7K 1/16W 5% 0402; AGILE_PN: 470-75626; CAD_APPROVED: Yes; EN: 101-1-02785; FPLIST: RC0402_25,RC0402_HD,0402_CC,RC0402_X2; HEIGHT: 0.41mm; MFG_NAME01: NIC COMPONENTS CORP; MFG_PN01: NRCL04J472TRF; ROHS: Yes; TOL: 5%; Tolerance: 5%
R235 R236 = RES: RES MF 499 OHM 1/10W 1% AEC-Q200 0402; AGILE_PN: 470-81550; CAD_APPROVED: Yes; EN: 101-1-00264; FPLIST: RC0402_25,RC0402_HD,0402_CC; HEIGHT: 0.40 MM; MFG_NAME01: KOA SPEER; MFG_PN01: RK73H1ETTP4990F; ROHS: Yes; TOL: 1%; Temp_Range: -55C to +155C; Tolerance: 1%
R238 = RES: RES MF 1M 1/16W 1% 0402; AGILE_PN: 470-80575; CAD_APPROVED: Yes; EN: 101-1-00581; FPLIST: RC0402_25,RC0402_HD,0402_CC; HEIGHT: 0.4MM; MFG_NAME01: BOURNS; MFG_PN01: CR0402-FX-1004GLF; ROHS: Yes; TOL: 1%; Tolerance: 1%
R241 = RES: RES MF 1M 1/16W 1% 0402; AGILE_PN: 470-80575; ASSY_OPT: DNP; CAD_APPROVED: Yes; EN: 101-1-00581; FPLIST: RC0402_25,RC0402_HD,0402_CC; HEIGHT: 0.4MM; MFG_NAME01: BOURNS; MFG_PN01: CR0402-FX-1004GLF; ROHS: Yes; TOL: 1%; Tolerance: 1%
U1-U6 = PUSB3F96_DFN2510A_10P: DIODE ESD TVS ARRAY USB2 USB3 5.5V 4A DFN2510A-10; AGILE_PN: 480-79837; CAD_APPROVED: Yes; EN: 301-0-01726; HEIGHT: 0.5MM; MFG_NAME01: NEXPERIA; MFG_PN01: IP4292CZ10-TBR,115; ROHS: Yes; Temp_Range: -40C to +85C
U7 = AP2331SA: IC SW CURRENT LIMITED FOR USB 0.4A 2.7-5.2V SOT23; AGILE_PN: 315-81584; CAD_APPROVED: Yes; EN: 301-0-01810; HEIGHT: 1.2 MM; MFG_NAME01: Diodes Inc; ROHS: Yes
C59 C168 C209 C500 C508 = CAP_NP: CAP CER 4.7uF 10V 10% X5R 0402; AGILE_PN: 150-79778; CAD_APPROVED: Yes; EN: 102-1-02063; FPLIST: CC0402_25,CC0402_HD,0402_CC; HEIGHT: 0.65MM; MFG_NAME01: TDK; MFG_PN01: C1005X5R1A475K050BC; ROHS: Yes; TOL: 10%; Tolerance: 10%; VOLTAGE: 10V
C220 C221 = CAP_POL: CAP ALEL 100UF 10V 20% -- AEC-Q200 SMT; AGILE_PN: 150-80100; CAD_APPROVED: Yes; EN: 102-3-00006; HEIGHT: 5.5MM; MFG_NAME01: PANASONIC; MFG_PN01: EEE-1AA101SP; ROHS: Yes; TOL: 20%; Temp_Range: -40C to +85C; Tolerance: 20%; VOLTAGE: 10V
C227 C228 = CAP_NP: CAP CER 1000PF 50V X7R 5% 0402; AGILE_PN: 150-75774; CAD_APPROVED: Yes; EN: 102-1-00054; FPLIST: CC0402_25,CC0402_HD,0402_CC; HEIGHT: 0.6MM; MFG_NAME01: CAPAX TECHNOLOGIES INC.; MFG_PN01: 0402X102J500SNT; ROHS: Yes; TOL: 5%; Tolerance: 5%; VOLTAGE: 50V
D25-D28 = DIODE_BIDIR: DIODE BIDIR ESD PROT 3.5pF 5V 1A SOD-962; AGILE_PN: 480-79836; CAD_APPROVED: Yes; EN: 305-1-00289; HEIGHT: 0.32MM; MFG_NAME01: NEXPERIA; MFG_PN01: PESD5V0V1BSF,315; ROHS: Yes; Temp_Range: -55°C to +150°C
FB3-FB5 = INDUCTOR_FERRITE: IND FER BEAD 120 OHM@100MHZ 1.3A 25% 0402; AGILE_PN: 180-77770; CAD_APPROVED: Yes; EN: 104-1-00007; FPLIST: IND_0402,0402_CC; HEIGHT: 0.55MM; MFG_NAME01: Murata; MFG_PN01: BLM15PD121SN1D; PART_TYPE: FERRITE\BEAD; ROHS: Yes; TOL: 25%; Tolerance: 25%
J15 = CONN_AUDIOJACK_4P: CON 4 AUD JACK RA SMT 3.5MM AG 205H BLACK; AGILE_PN: 211-80155; CAD_APPROVED: Yes; EN: 201-2-00370; HEIGHT: 5.2MM; MFG_NAME01: CUI INC; MFG_PN01: SJ-43515TS-SMT-TR; ROHS: Yes; Temp_Range: -25C to +85C
R180 = RES: RES MF 2.2K 1/16W 5% 0402; AGILE_PN: 470-75636; CAD_APPROVED: Yes; EN: 101-1-02777; FPLIST: RC0402_25,RC0402_HD,0402_CC; HEIGHT: 0.4 MM; MFG_NAME01: BOURNS; MFG_PN01: CR0402-JW-222GLF; ROHS: Yes; TOL: 5%; Tolerance: 5%
R181 = RES: RES MF 33K 1/10W 1% AEC-Q200 0402; AGILE_PN: 470-81714; CAD_APPROVED: Yes; EN: 101-1-03395; FPLIST: RC0402_25,RC0402_HD,0402_CC; HEIGHT: 0.40 MM; MFG_NAME01: KOA SPEER; MFG_PN01: RK73H1ETTP3302F; ROHS: Yes; TOL: 1%; Temp_Range: -55C to +155C; Tolerance: 1%
R102 R104 R182 R251 R271 R328 R333 R348 R356 = RES: RES MF 10.0K 1/16W 1% 0402; AGILE_PN: 470-80574; CAD_APPROVED: Yes; EN: 101-1-00389; FPLIST: RC0402_25,RC0402_HD,0402_CC; HEIGHT: 0.4MM; MFG_NAME01: WALSIN TECHNOLOGY CORP.; MFG_PN01: WR04X1002FTL; ROHS: Yes; TOL: 1%; Tolerance: 1%
TP61 TP66 TP69 TP71 TP74 TP85 = TESTLOOP: TEST POINT PAD 50MIL DIA SMT, NO PART TO ORDER; AGILE_PN: 211-76644; CAD_APPROVED: Yes; HEIGHT: 0.1MM; MFG_NAME01: NOTACOMPONENT; MFG_PN01: NOTACOMPONENT; ROHS: Yes
U29 = WM8960_QFN_33P: IC CODEC STEREO WITH CLASS D SPEAKER DRIVER 1.71-3.6V QFN32; AGILE_PN: 315-79450; CAD_APPROVED: Yes; EN: 301-0-01482; HEIGHT: 1MM; MFG_NAME01: WOLFSON MICROELECTRONICS; MFG_PN01: WM8960CGEFL/RV; ROHS: Yes
C52 C58 C244-C246 C250-C255 C260-C262 C266-C271 C373 C444 = CAP_NP: CAP CER 10UF 10V 20% X5R 0603; AGILE_PN: 150-78609; CAD_APPROVED: Yes; EN: 102-1-01640; FPLIST: CC0603_OV,CC0603,0603_CC; HEIGHT: 1.016MM; MFG_NAME01: TAIYO YUDEN; MFG_PN01: LMK107BJ106MALTD; ROHS: Yes; VOLTAGE: 10V
D6 D7 = LED: LED RED SGL 20MA 0603; AGILE_PN: 370-76632; CAD_APPROVED: Yes; EN: 106-4-00247; HEIGHT: 0.45MM; MFG_NAME01: LITE ON; MFG_PN01: LTST-C193KRKT-5A; ROHS: Yes
FL5 = DLW43: IND CHK 90 OHM@100MHZ 330MA 25% 0805; AGILE_PN: 180-76336; CAD_APPROVED: Yes; EN: 303-0-00024; HEIGHT: 1MM; MFG_NAME01: MURATA; MFG_PN01: DLW21HN900SQ2L; PART_TYPE: CHOKE; ROHS: Yes; TOL: 25%; Tolerance: 25%
J12 = CON_67_FEMALE_RA: CON 67 M.2 NGFF MINI CARD DOUBLE SIDE RA SMT 0.5MM SP 165H AU; AGILE_PN: 211-80173; CAD_APPROVED: Yes; EN: 201-2-00909; HEIGHT: 4.2 MM; MFG_NAME01: TE Connectivity Ltd; MFG_PN01: 2199230-4; ROHS: Yes; Temp_Range: -40C to 80C
R80 R194 R195 R207-R209 R212-R214 = RES: RES MF ZERO OHM 1/16W -- AEC-Q200 0402; AGILE_PN: 470-80742; ASSY_OPT: DNP; CAD_APPROVED: Yes; EN: 101-1-00001; FPLIST: RC0402_25,RC0402_HD,0402_CC; HEIGHT: 0.45 MM; MFG_NAME01: VISHAY INTERTECHNOLOGY; MFG_PN01: CRCW04020000Z0ED; ROHS: Yes
R84 = RES: RES MF 499K  1/16W 1% 0402; AGILE_PN: 470-31139; CAD_APPROVED: Yes; EN: 101-1-00552; FPLIST: RC0402_25,RC0402_HD,0402_CC; HEIGHT: 0.40 MM; MFG_NAME01: YAGEO AMERICA; MFG_PN01: RC0402FR-07499KL; ROHS: Yes; TOL: 1%; Tolerance: 1%
R85 R87 R90 R98 R103 R250 R256 R257 R262 R263 = RES: RES MF 10.0K 1/16W 1% 0402; AGILE_PN: 470-80574; ASSY_OPT: DNP; CAD_APPROVED: Yes; EN: 101-1-00389; FPLIST: RC0402_25,RC0402_HD,0402_CC; HEIGHT: 0.4MM; MFG_NAME01: WALSIN TECHNOLOGY CORP.; MFG_PN01: WR04X1002FTL; ROHS: Yes; TOL: 1%; Tolerance: 1%
R93-R96 = RES: RES MF 100 OHM 1/16W 5% AEC-Q200 0402; AGILE_PN: 470-80555; CAD_APPROVED: Yes; EN: 101-1-02745; FPLIST: RC0402_25,RC0402_HD,RC0402_X2,0402_CC; HEIGHT: 0.45mm; MFG_NAME01: VISHAY INTERTECHNOLOGY; MFG_PN01: CRCW0402100RJNED; ROHS: Yes
U13 = FXAS21002CQ_QFN_24P: IC XTRINSIC 3-AXIS DIGITAL GYROSCOPE 1.95-3.6V QFN24; AGILE_PN: 312-81029; CAD_APPROVED: Yes; EN: 304-1-00087; HEIGHT: 1.1 MM; MFG_NAME01: FREESCALE SEMICONDUCTOR; ROHS: Yes
U14 = PPL3115A2_LGA_8P: IC ALTIMETER I2C 50-115KPA 1.96-3.6V LGA8; AGILE_PN: 315-79136; CAD_APPROVED: Yes; EN: 304-1-00147; HEIGHT: 1.2MM; MFG_NAME01: FREESCALE SEMICONDUCTOR; ROHS: Yes
U19 = NC7SZ14: IC INV SGL 1.65-5.5V TSSOP5; AGILE_PN: 315-81077; CAD_APPROVED: Yes; EN: 301-0-01255; HEIGHT: 1.1MM; MFG_NAME01: NEXPERIA; MFG_PN01: 74LVC1G04GW,125; ROHS: Yes
U20 = ISL29023: IC LIGHT SENSOR I2C 16-BIT 2.25-3.63V ODFN6; AGILE_PN: 315-79130; CAD_APPROVED: Yes; EN: 304-1-00148; HEIGHT: 0.75MM; MFG_NAME01: Intersil; MFG_PN01: ISL29023IROZ-T7; ROHS: Yes
U21 = FXOS8700CQ_QFN_16P: IC ACCELEROMETER AND MAGNETOMETER SENSOR 3-AXIS 2.5V QFN16; AGILE_PN: 312-80418; CAD_APPROVED: Yes; EN: 304-1-00146; FPLIST: QFN5X3_0P5_3X3,QFN5X3_0P5_3X3_a; HEIGHT: 1.25MM; MFG_NAME01: Freescale Semiconductor; ROHS: Yes
U22 = 1G125: IC BUFFER/LINE DRIVER 3STATE 0.8-3.6V SC70-5; AGILE_PN: 315-80956; CAD_APPROVED: Yes; EN: 301-0-01520; HEIGHT: 1.1MM; MFG_NAME01: NEXPERIA; MFG_PN01: 74AUP1G125GW,125; ROHS: Yes
C240 C242 C243 C256 C258 C259 = CAP_NP: CAP CER 10uF 25V 20% X5R 0603; AGILE_PN: 150-79272; CAD_APPROVED: Yes; EN: 102-1-01982; FPLIST: CC0603_OV,CC0603,0603_CC; HEIGHT: 1MM; MFG_NAME01: Murata; MFG_PN01: GRM188R61E106MA73D; ROHS: Yes; TOL: 20%; Tolerance: 20%; VOLTAGE: 25V
J2 J3 J5 J7 J8 J10 = CONN_36_SH8_A: CON 36 MINISAS SHLD 0.8MM SP 800H AU 77L; AGILE_PN: 211-80162; CAD_APPROVED: Yes; EN: 201-1-00825; HEIGHT: 20.31MM; MFG_NAME01: MOLEX; ROHS: Yes
R203 R220 = RES: RES MF 68K 1/16W 5% 0402; AGILE_PN: 470-30330; CAD_APPROVED: Yes; EN: 101-1-02813; FPLIST: RC0402_25,RC0402_HD,0402_CC; HEIGHT: 0.4MM; MFG_NAME01: TYCO ELECTRONICS; MFG_PN01: CRG0402J68K; ROHS: Yes; TOL: 5%; Tolerance: 5%
R242 R245 = RES: RES MF 18 OHM 1/16W 5% 0402; AGILE_PN: 470-30516; CAD_APPROVED: Yes; EN: 101-1-02727; FPLIST: RC0402_25,RC0402_HD,0402_CC; HEIGHT: 0.45 MM; MFG_NAME01: VISHAY INTERTECHNOLOGY; MFG_PN01: CRCW040218R0JNED; ROHS: Yes; TOL: %5; Tolerance: %5
U11 U16 = PCA9511ADP_8P: IC HOT SWAP I2C 0-400KHZ 2.7-5.5V TSSOP8; AGILE_PN: 315-80932; CAD_APPROVED: Yes; EN: 301-0-02056; HEIGHT: 1.1 MM; MFG_NAME01: NXP SEMICONDUCTORS; MFG_PN01: PCA9511ADP,118; ROHS: Yes
U25 U27 U43 U46 = NC7WV16_6P: IC BUFFER NON-INVERTING DUAL 0.9-3.6V SC70-6; AGILE_PN: 312-80921; CAD_APPROVED: Yes; EN: 301-0-01510; HEIGHT: 1.1MM; MFG_NAME01: Fairchild; MFG_PN01: NC7WV16P6X; ROHS: Yes
U40 = NTB0104BQ: IC DUAL XLTR XCVR 4BIT 1.2-3.6/1.65-5.5V DHVQFN14; AGILE_PN: 312-81227; CAD_APPROVED: Yes; EN: 301-0-01247; HEIGHT: 1MM; MFG_NAME01: NXP SEMICONDUCTORS; MFG_PN01: NTB0104BQ,115; ROHS: Yes

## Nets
GND: C1.2 C2.1 C3.1 C4.1 C5.2 C6.1 C7.2 C39.1 C48.1 C49.1 C50.2 C52.2 C53.1 C54.2 C55.1 C58.2 C59.2 C60.1 C61.2 C62.1 C64.1 C65.1 C66.2 C68.2 C69.2 C88.2 C120.1 C127.1 C240.1 C242.1 C243.1 C244.1 C245.1 C246.1 C250.1 C251.1 C252.1 C253.1 C254.1 C255.1 C256.1 C258.1 C259.1 C260.1 C261.1 C262.1 C266.1 C267.1 C268.1 C269.1 C270.1 C271.1 C274.2 C275.2 C291.2 C373.1 C379.1 C444.1 C451.1 C465.2 C470.2 J1.2 J1.5 J1.8 J1.11 J2.A1 J2.A4 J2.A7 J2.A12 J2.A15 J2.A18 J2.B1 J2.B4 J2.B7 J2.B12 J2.B15 J2.B18 J2.T1(SH1) J2.T2(SH2) J2.T3(SH3) J2.T4(SH4) J2.T5(SH5) J2.T6(SH6) J2.T7(SH7) J2.T8(SH8) J3.A1 J3.A4 J3.A7 J3.A12 J3.A15 J3.A18 J3.B1 J3.B4 J3.B7 J3.B12 J3.B15 J3.B18 J3.T1(SH1) J3.T2(SH2) J3.T3(SH3) J3.T4(SH4) J3.T5(SH5) J3.T6(SH6) J3.T7(SH7) J3.T8(SH8) J5.A1 J5.A4 J5.A7 J5.A12 J5.A15 J5.A18 J5.B1 J5.B4 J5.B7 J5.B12 J5.B15 J5.B18 J5.T1(SH1) J5.T2(SH2) J5.T3(SH3) J5.T4(SH4) J5.T5(SH5) J5.T6(SH6) J5.T7(SH7) J5.T8(SH8) J6.2 J6.5 J6.8 J6.11 J7.A1 J7.A4 J7.A7 J7.A12 J7.A15 J7.A18 J7.B1 J7.B4 J7.B7 J7.B12 J7.B15 J7.B18 J7.T1(SH1) J7.T2(SH2) J7.T3(SH3) J7.T4(SH4) J7.T5(SH5) J7.T6(SH6) J7.T7(SH7) J7.T8(SH8) J8.A1 J8.A4 J8.A7 J8.A12 J8.A15 J8.A18 J8.B1 J8.B4 J8.B7 J8.B12 J8.B15 J8.B18 J8.T1(SH1) J8.T2(SH2) J8.T3(SH3) J8.T4(SH4) J8.T5(SH5) J8.T6(SH6) J8.T7(SH7) J8.T8(SH8) J10.A1 J10.A4 J10.A7 J10.A12 J10.A15 J10.A18 J10.B1 J10.B4 J10.B7 J10.B12 J10.B15 J10.B18 J10.T1(SH1) J10.T2(SH2) J10.T3(SH3) J10.T4(SH4) J10.T5(SH5) J10.T6(SH6) J10.T7(SH7) J10.T8(SH8) J12.1(GND1) J12.7(GND2) J12.18(GND3) J12.33(GND5) J12.39(GND4) J12.45(GND6) J12.51(GND7) J12.57(GND8) J12.63(GND9) J12.69(GND10) J12.75(GND11) Q4.2(SOURCE) R8.2 R9.2 R74.1 R84.1 R102.1 R199.2 R217.2 R235.1 R236.1 R238.1 R241.2 R255.1 R271.1 R326.1 U1.3(GND1) U1.8(GND2) U2.3(GND1) U2.8(GND2) U3.3(GND1) U3.8(GND2) U4.3(GND1) U4.8(GND2) U5.3(GND1) U5.8(GND2) U6.3(GND1) U6.8(GND2) U7.1(GND) U11.4(GND) U13.1(GND1) U13.5(GND2) U13.6(RSVD1) U13.7(RSVD2) U13.9(RSVD3) U13.10(RSVD4) U13.14(GND3) U13.19(GND4) U13.20(RSVD5) U13.21(RSVD6) U13.22(RSVD7) U13.23(RSVD8) U13.24(RSVD9) U14.3(GND) U16.4(GND) U19.3(GND) U20.2(GND) U20.7(EP) U21.3(RSVD1) U21.5(GND1) U21.12(GND2) U21.13(RSVD2) U22.2(A) U22.3(GND) U25.2(GND) U27.2(GND) U29.9(DGND) U40.7(GND1) U40.15(GND2) U43.2(GND) U46.2(GND) ; also on sheet 2 5 6 10 11 12 13 14 16 17 18 19 20 21 22 23 24 32
VCC_1V8: C68.1 C120.2 C127.2 C274.1 C291.1 R107.2 R230.2 U22.5(VCC) U29.8(DCVDD) U29.10(DBVDD) U40.1(VCCA) U43.5(VCC) ; also on sheet 2 6 10 11 12 15 16 17 18 19 21 24
VCC_3V3: C1.1 C39.2 C49.2 C50.1 C52.1 C53.2 C55.2 C58.1 C59.1 C60.2 C61.1 C62.2 C64.2 C69.1 C208.2 D1.1(ANODE1) D2.1(ANODE1) R1.1 R2.1 R3.1 R4.2 R5.1 R6.1 R7.1 R73.2 R85.1 R87.1 R90.1 R98.1 R103.1 R104.1 R181.2 R231.1 R232.1 R250.2 R251.2 R256.1 R257.1 R262.1 R263.1 U11.8(VCC) U13.15(VDD) U13.18(VDDIO) U14.1(VDD) U14.4(VDDIO) U16.8(VCC) U19.5(VCC) U20.1(VDD) U21.1(VDDIO) U21.14(VDD) U29.32(AVDD) ; also on sheet 6 10 12 18 20 22 23 24
VCC_12V0: C240.2 C242.2 C243.2 C256.2 C258.2 C259.2 J2.A8 J2.A9 J3.A8 J3.A9 J5.A8 J5.A9 J7.A8 J7.A9 J8.A8 J8.A9 J10.A8 J10.A9 ; also on sheet 2 5 10 22
VCC_BB_ENT1IO: C88.1 C465.1 C470.1 U25.5(VCC) U27.5(VCC) U46.5(VCC) ; also on sheet 2 12
VCC_EXT_1V8: C244.2 C250.2 C253.2 C260.2 C266.2 C269.2 J2.A5 J2.A6 J3.A5 J3.A6 J5.A5 J5.A6 J7.A5 J7.A6 J8.A5 J8.A6 J10.A5 J10.A6 R197.2 R198.2 R203.1 R204.2 R205.2 R218.2 R219.2 R220.1 R221.2 R222.2 ; also on sheet 2 5 6 10 14
VCC_HDMI_5V0: C4.2 J1.18 R202.2 R210.2 R229.2 U15.BN11(HDMI_RX0_MON_5V)
VCC_PCIE_1V8: Q4.1(GATE) ; also on sheet 12 23
VCC_PER_3V3: C245.2 C251.2 C254.2 C261.2 C267.2 C270.2 C275.1 C373.2 C379.2 C444.2 C451.2 J2.A13 J2.A14 J3.A13 J3.A14 J5.A13 J5.A14 J7.A13 J7.A14 J8.A13 J8.A14 J10.A13 J10.A14 J12.2(3V3_1) J12.4(3V3_2) J12.72(3V3_3) J12.74(3V3_4) R225.2 R226.2 R272.2 R273.2 R275.2 U40.14(VCCB) ; also on sheet 2 5 6
VCC_PER_5V0: C2.2 C246.2 C252.2 C255.2 C262.2 C268.2 C271.2 C500.1 C508.1 J2.A16 J2.A17 J3.A16 J3.A17 J5.A16 J5.A17 J7.A16 J7.A17 J8.A16 J8.A17 J10.A16 J10.A17 U7.3(IN) U29.21(SPKVDD2) U29.26(SPKVDD1) ; also on sheet 2 5 6 22
VCC_TX_5V0: C3.2 C6.2 J6.18 R10.2 R11.2 U7.2(OUT)
AUD_DET_1V8(SCU_GPIO0_03): TP85.1(Pin1) U29.15(ADCLRC/GPIO1) ; also on sheet 14
AUD_GND: C168.2 C208.1 C209.2 C227.2 C228.2 C500.2 C508.2 D25.2(C2) D26.2(C2) D27.2(C2) D28.2(C2) J15.4(RING2) R182.1 R326.2 R328.2 R333.2 R348.2 R356.2 U29.20(SPKGND2) U29.24(SPKGND1) U29.28(AGND) U29.33(GND_PADDLE)
BB_ENET1_RGMII_TX_CTL: U27.4(Y2) ; also on sheet 2
BB_ENET1_RGMII_TXC: U27.6(Y1) ; also on sheet 2
BB_ENET1_RGMII_TXD0: U25.6(Y1) ; also on sheet 2
BB_ENET1_RGMII_TXD1: U25.4(Y2) ; also on sheet 2
BB_ENET1_RGMII_TXD2: U46.6(Y1) ; also on sheet 2
BB_ENET1_RGMII_TXD3: U46.4(Y2) ; also on sheet 2
BB_ESAI0_MCLK: R242.2 ; also on sheet 2
BB_GPIO_1V8(LVDS1_I2C0_SCL): U15.BL35(LVDS1_I2C0_SCL) ; also on sheet 2
BB_I2C0_3V3_SCL: R1.2 U16.2(SCLOUT) ; also on sheet 2
BB_I2C0_3V3_SDA: R2.2 U16.7(SDAOUT) ; also on sheet 2
BB_I2C4_3V3_SCL: R6.2 U11.2(SCLOUT) ; also on sheet 2
BB_I2C4_3V3_SDA: R5.2 U11.7(SDAOUT) ; also on sheet 2
BB_PER_RST_B: U40.11(B3) ; also on sheet 2
BB_PER_RST_B_1V8: U40.4(A3) ; also on sheet 20
BPASS: C65.2 U21.2(BYP)
BT_DISABLE_B: J12.54(~{W_DISABLE2}) ; also on sheet 19
BT_LED2_B: D6.C(CATHODE) J12.16(~{LED2})
BT_SAI0_RXD(SAI1_RXFS): J12.12(I2S_SD_IN) ; also on sheet 14
BT_SAI0_TXC(SPI0_CS1): J12.8(I2S_SCK) ; also on sheet 14
BT_SAI0_TXD(SAI1_RXC): J12.14(I2S_SD_OUT) ; also on sheet 14
BT_SAI0_TXFS(SPI2_CS1): J12.10(I2S_WS) ; also on sheet 14
BT_UART1_CTS: J12.34(UART_CTS) ; also on sheet 15
BT_UART1_RTS: J12.36(UART_RTS) ; also on sheet 15
BT_UART1_RX: J12.22(UART_RXD) ; also on sheet 15
BT_UART1_TX: J12.32(UART_TXD) ; also on sheet 15
BT_WAKE(USB_SS3_TC2): J12.20(~{UART_WAKE}) ; also on sheet 22
CAP_EXT: C54.1 U14.2(CAP)
CPU_PER_RST_3V3: U13.4(~{RST}) U19.2(A) U40.10(B4) ; also on sheet 24
CPU_PER_RST_B_1V8: U40.5(A4) ; also on sheet 18 20
CRST: C66.1 U21.8(CRST)
D_MIC: D27.1(C1) FB5.2 J15.1(SLEEVE)
ENET1_RGMII_TX_CTL: U27.3(A2) ; also on sheet 24
ENET1_RGMII_TXC: U27.1(A1) ; also on sheet 24
ENET1_RGMII_TXD0: U25.1(A1) ; also on sheet 24
ENET1_RGMII_TXD1: U25.3(A2) ; also on sheet 24
ENET1_RGMII_TXD2: U46.1(A1) ; also on sheet 24
ENET1_RGMII_TXD3: U46.3(A2) ; also on sheet 24
GY_INT1_B: R81.1 R262.2 U13.3(INT1)
GY_INT2_B: R80.1 R263.2 U13.2(INT2/PWR_CTRL)
GYR_CS_B: R251.1 U13.17(~{SPI_CS})
GYR_I2C_A0: R250.1 R255.2 U13.13(SA0/MISO)
GYR_I2C_B: R74.2 U13.8(~{I2C}/SPI)
GYR_INT_B: R80.2 R81.2 R94.2
H_OUTL: D28.1(C1) FB4.2 J15.2(TIP) R182.2
H_OUTR: D26.1(C1) FB3.2 J15.3(RING1)
HDMI_DDC_SCL: J1.15 R210.1 U15.BH10(HDMI_RX0_DDC_SCL)
HDMI_DDC_SDA: J1.16 R202.1 U15.BE13(HDMI_RX0_DDC_SDA)
HDMI_RX0_ARC_P: C556.1 U15.BM14(HDMI_RX0_ARC_P)
HDMI_RX0_ARC_P_CON: C556.2 J1.14 U3.2(CH2) U3.9(NC3)
HDMI_RX0_CEC: J1.13 R196.1 U3.1(CH1) U3.10(NC4) U15.BJ9(HDMI_RX0_CEC)
HDMI_RX0_CLK_N: J1.12 U2.5(CH4) U2.6(NC1) U15.BL11(HDMI_RX0_CLK_N)
HDMI_RX0_CLK_P: J1.10 U2.4(CH3) U2.7(NC2) U15.BM12(HDMI_RX0_CLK_P)
HDMI_RX0_DAT0_N: J1.9 U2.2(CH2) U2.9(NC3) U15.BL15(HDMI_RX0_DATA0_N)
HDMI_RX0_DAT0_P: J1.7 U2.1(CH1) U2.10(NC4) U15.BM16(HDMI_RX0_DATA0_P)
HDMI_RX0_DAT1_N: J1.6 U1.5(CH4) U1.6(NC1) U15.BL17(HDMI_RX0_DATA1_N)
HDMI_RX0_DAT1_P: J1.4 U1.4(CH3) U1.7(NC2) U15.BM18(HDMI_RX0_DATA1_P)
HDMI_RX0_DAT2_N: J1.3 U1.2(CH2) U1.9(NC3) U15.BL19(HDMI_RX0_DATA2_N)
HDMI_RX0_DAT2_P: J1.1 U1.1(CH1) U1.10(NC4) U15.BM20(HDMI_RX0_DATA2_P)
HDMI_RX0_HPD: J1.19 R229.1 R241.1 U3.5(CH4) U3.6(NC1) U15.BF14(HDMI_RX0_HPD)
HDMI_TX0_ARC_P: C37.2 J6.14 U6.2(CH2) U6.9(NC3)
HDMI_TX0_AUX_ARC_P: C37.1 U15.BH2(HDMI_TX0_AUX_P)
HDMI_TX0_CEC: J6.13 R50.1 U6.1(CH1) U6.10(NC4) U15.BJ1(HDMI_TX0_CEC)
HDMI_TX0_CLK_EDP3_N: C35.1 U15.BK2(HDMI_TX0_CLK_EDP3_N)
HDMI_TX0_CLK_EDP3_P: C33.1 U15.BL3(HDMI_TX0_CLK_EDP3_P)
HDMI_TX0_CLK_N: FL4.2 J6.12 U5.5(CH4) U5.6(NC1)
HDMI_TX0_CLK_P: FL4.3 J6.10 U5.4(CH3) U5.7(NC2)
HDMI_TX0_DAT0_EDP2_N: C25.1 U15.BM4(HDMI_TX0_DATA0_EDP2_N)
HDMI_TX0_DAT0_EDP2_P: C24.1 U15.BL5(HDMI_TX0_DATA0_EDP2_P)
HDMI_TX0_DAT0_N: FL3.2 J6.9 U5.2(CH2) U5.9(NC3)
HDMI_TX0_DAT0_P: FL3.3 J6.7 U5.1(CH1) U5.10(NC4)
HDMI_TX0_DAT1_EDP1_N: C27.1 U15.BM6(HDMI_TX0_DATA1_EDP1_N)
HDMI_TX0_DAT1_EDP1_P: C26.1 U15.BL7(HDMI_TX0_DATA1_EDP1_P)
HDMI_TX0_DAT1_N: FL2.2 J6.6 U4.5(CH4) U4.6(NC1)
HDMI_TX0_DAT1_P: FL2.3 J6.4 U4.4(CH3) U4.7(NC2)
HDMI_TX0_DAT2_EDP0_N: C29.1 U15.BM8(HDMI_TX0_DATA2_EDP0_N)
HDMI_TX0_DAT2_EDP0_P: C28.1 U15.BL9(HDMI_TX0_DATA2_EDP0_P)
HDMI_TX0_DAT2_N: FL1.2 J6.3 U4.2(CH2) U4.9(NC3)
HDMI_TX0_DAT2_P: FL1.3 J6.1 U4.1(CH1) U4.10(NC4)
HDMI_TX0_DDC_SCL: J6.15 R10.1 U6.4(CH3) U6.7(NC2) U15.BG1(HDMI_TX0_DDC_SCL)
HDMI_TX0_DDC_SDA: J6.16 R11.1 U6.5(CH4) U6.6(NC1) U15.BN5(HDMI_TX0_DDC_SDA)
HDMI_TX0_HPD: J6.19 R238.2 U3.4(CH3) U3.7(NC2) U15.BH8(HDMI_TX0_HPD)
HDMI_TX_CLK_N: C35.2 FL4.1 R48.2
HDMI_TX_CLK_P: C33.2 FL4.4 R45.2
HDMI_TX_DAT0_N: C25.2 FL3.1 R35.2
HDMI_TX_DAT0_P: C24.2 FL3.4 R34.2
HDMI_TX_DAT1_N: C27.2 FL2.1 R37.2
HDMI_TX_DAT1_P: C26.2 FL2.4 R36.2
HDMI_TX_DAT2_N: C29.2 FL1.1 R39.2
HDMI_TX_DAT2_P: C28.2 FL1.4 R38.2
HP_DETECT: D25.1(C1) J15.5(TIP_SWITCH) R181.1 U29.2(LINPUT3/JD2)
HP_LEFT: C221.1 U29.31(HP_L)
HP_OUTL: C221.2 C228.1 FB4.1
HP_OUTR: C220.2 C227.1 FB3.1
HP_RIGHT: C220.1 U29.29(HP_R)
I2C0_3V3_SCL: R69.2 R71.2 R83.2 R92.2 R232.2 U15.BN9(HDMI_TX0_TS_SCL) U16.3(SCLIN) ; also on sheet 22
I2C0_3V3_SDA: R70.2 R72.2 R82.2 R100.2 R231.2 U15.BN7(HDMI_TX0_TS_SDA) U16.6(SDAIN) ; also on sheet 22
I2C1_1V8_SCL: R267.2 U29.17(SCLK) ; also on sheet 15
I2C1_1V8_SDA: R268.2 U29.18(SDIN) ; also on sheet 15
I2C4_3V3_SCL: U11.3(SCLIN) ; also on sheet 24
I2C4_3V3_SDA: U11.6(SDAIN) ; also on sheet 24
I2C_A0: R102.2 R103.2 U21.7(SA0/MISO)
I2C_A1: R90.2 R271.2 U21.10(SA1/~{CS})
LIGHT_INT_B: R85.2 R96.2 U20.4(~{INT})
LINPUT2: R356.1 U29.3(LINPUT2)
LVDS0_BL_PWM: J7.B8 R206.1 U15.BE39(LVDS0_GPIO00)
LVDS0_CH0_CLK_N: J7.A2 U15.BL41(LVDS0_CH0_CLK_N)
LVDS0_CH0_CLK_P: J7.A3 U15.BN41(LVDS0_CH0_CLK_P)
LVDS0_CH0_TX0_N: J7.B2 U15.BK42(LVDS0_CH0_TX0_N)
LVDS0_CH0_TX0_P: J7.B3 U15.BM42(LVDS0_CH0_TX0_P)
LVDS0_CH0_TX1_N: J7.B5 U15.BL43(LVDS0_CH0_TX1_N)
LVDS0_CH0_TX1_P: J7.B6 U15.BN43(LVDS0_CH0_TX1_P)
LVDS0_CH0_TX2_N: J7.B13 U15.BK44(LVDS0_CH0_TX2_N)
LVDS0_CH0_TX2_P: J7.B14 U15.BM44(LVDS0_CH0_TX2_P)
LVDS0_CH0_TX3_N: J7.B16 U15.BL45(LVDS0_CH0_TX3_N)
LVDS0_CH0_TX3_P: J7.B17 U15.BN45(LVDS0_CH0_TX3_P)
LVDS0_CH1_CLK_N: J2.A2 U15.BG45(LVDS0_CH1_CLK_N)
LVDS0_CH1_CLK_P: J2.A3 U15.BH46(LVDS0_CH1_CLK_P)
LVDS0_CH1_TX0_N: J2.B2 U15.BG43(LVDS0_CH1_TX0_N)
LVDS0_CH1_TX0_P: J2.B3 U15.BH44(LVDS0_CH1_TX0_P)
LVDS0_CH1_TX1_N: J2.B5 U15.BG41(LVDS0_CH1_TX1_N)
LVDS0_CH1_TX1_P: J2.B6 U15.BH42(LVDS0_CH1_TX1_P)
LVDS0_CH1_TX2_N: J2.B13 U15.BG39(LVDS0_CH1_TX2_N)
LVDS0_CH1_TX2_P: J2.B14 U15.BH40(LVDS0_CH1_TX2_P)
LVDS0_CH1_TX3_N: J2.B16 U15.BG37(LVDS0_CH1_TX3_N)
LVDS0_CH1_TX3_P: J2.B17 U15.BH38(LVDS0_CH1_TX3_P)
LVDS0_TS_INT: J7.B9 R207.1 U15.BD40(LVDS0_GPIO01)
LVDS0_TS_SCL: J7.B11 R209.1 R219.1 U15.BE37(LVDS0_I2C1_SCL)
LVDS0_TS_SDA: J7.B10 R208.1 R218.1 U15.BE35(LVDS0_I2C1_SDA)
LVDS1_BL_PWM: J8.B8 R211.1 U15.BD34(LVDS1_GPIO00)
LVDS1_CH0_CLK_N: J8.A2 U15.BK36(LVDS1_CH0_CLK_N)
LVDS1_CH0_CLK_P: J8.A3 U15.BM36(LVDS1_CH0_CLK_P)
LVDS1_CH0_TX0_N: J8.B2 U15.BL37(LVDS1_CH0_TX0_N)
LVDS1_CH0_TX0_P: J8.B3 U15.BN37(LVDS1_CH0_TX0_P)
LVDS1_CH0_TX1_N: J8.B5 U15.BK38(LVDS1_CH0_TX1_N)
LVDS1_CH0_TX1_P: J8.B6 U15.BM38(LVDS1_CH0_TX1_P)
LVDS1_CH0_TX2_N: J8.B13 U15.BL39(LVDS1_CH0_TX2_N)
LVDS1_CH0_TX2_P: J8.B14 U15.BN39(LVDS1_CH0_TX2_P)
LVDS1_CH0_TX3_N: J8.B16 U15.BK40(LVDS1_CH0_TX3_N)
LVDS1_CH0_TX3_P: J8.B17 U15.BM40(LVDS1_CH0_TX3_P)
LVDS1_CH1_CLK_N: J3.A2 U15.BK34(LVDS1_CH1_CLK_N)
LVDS1_CH1_CLK_P: J3.A3 U15.BM34(LVDS1_CH1_CLK_P)
LVDS1_CH1_TX0_N: J3.B2 U15.BL33(LVDS1_CH1_TX0_N)
LVDS1_CH1_TX0_P: J3.B3 U15.BN33(LVDS1_CH1_TX0_P)
LVDS1_CH1_TX1_N: J3.B5 U15.BK32(LVDS1_CH1_TX1_N)
LVDS1_CH1_TX1_P: J3.B6 U15.BM32(LVDS1_CH1_TX1_P)
LVDS1_CH1_TX2_N: J3.B13 U15.BL31(LVDS1_CH1_TX2_N)
LVDS1_CH1_TX2_P: J3.B14 U15.BN31(LVDS1_CH1_TX2_P)
LVDS1_CH1_TX3_N: J3.B16 U15.BK30(LVDS1_CH1_TX3_N)
LVDS1_CH1_TX3_P: J3.B17 U15.BM30(LVDS1_CH1_TX3_P)
LVDS1_TS_INT: J8.B9 R212.1 U15.BH36(LVDS1_GPIO01)
LVDS1_TS_SCL: J8.B11 R198.1 R214.1 U15.BD32(LVDS1_I2C1_SCL)
LVDS1_TS_SDA: J8.B10 R197.1 R213.1 U15.BN35(LVDS1_I2C1_SDA)
LVDS_EN: J7.A11 J8.A11 R194.1 R195.1 U15.BD38(LVDS0_I2C0_SCL)
MCLK_ESAI0: R242.1 U43.4(Y2)
MCLK_OUT0: U43.1(A1) U43.3(A2) ; also on sheet 14
MIC: C229.1 U29.4(LINPUT1)
MICBIAS: C168.1 R180.1 U29.1(MICBIAS)
MIPI_CSI0_CLK_N: J10.A2 U15.BE21(MIPI_CSI0_CLK_N)
MIPI_CSI0_CLK_P: J10.A3 U15.BF20(MIPI_CSI0_CLK_P)
MIPI_CSI0_DATA0_N: J10.B2 U15.BE23(MIPI_CSI0_DATA0_N)
MIPI_CSI0_DATA0_P: J10.B3 U15.BF22(MIPI_CSI0_DATA0_P)
MIPI_CSI0_DATA1_N: J10.B5 U15.BE19(MIPI_CSI0_DATA1_N)
MIPI_CSI0_DATA1_P: J10.B6 U15.BF18(MIPI_CSI0_DATA1_P)
MIPI_CSI0_DATA2_N: J10.B13 U15.BE25(MIPI_CSI0_DATA2_N)
MIPI_CSI0_DATA2_P: J10.B14 U15.BF24(MIPI_CSI0_DATA2_P)
MIPI_CSI0_DATA3_N: J10.B16 U15.BE17(MIPI_CSI0_DATA3_N)
MIPI_CSI0_DATA3_P: J10.B17 U15.BF16(MIPI_CSI0_DATA3_P)
MIPI_CSI0_EN: J10.A11 U15.BM22(MIPI_CSI0_GPIO0_01)
MIPI_CSI0_I2C0_SCL: J10.B11 R222.1 U15.BH24(MIPI_CSI0_I2C0_SCL)
MIPI_CSI0_I2C0_SDA: J10.B10 R221.1 U15.BN19(MIPI_CSI0_I2C0_SDA)
MIPI_CSI0_MCLK_OUT: J10.B8 U15.BJ23(MIPI_CSI0_MCLK_OUT)
MIPI_CSI0_RST_B: J10.B9 R220.2 U15.BL23(MIPI_CSI0_GPIO0_00)
MIPI_CSI1_CLK_N: J5.A2 U15.BH16(MIPI_CSI1_CLK_N)
MIPI_CSI1_CLK_P: J5.A3 U15.BJ17(MIPI_CSI1_CLK_P)
MIPI_CSI1_DATA0_N: J5.B2 U15.BH18(MIPI_CSI1_DATA0_N)
MIPI_CSI1_DATA0_P: J5.B3 U15.BJ19(MIPI_CSI1_DATA0_P)
MIPI_CSI1_DATA1_N: J5.B5 U15.BH14(MIPI_CSI1_DATA1_N)
MIPI_CSI1_DATA1_P: J5.B6 U15.BJ15(MIPI_CSI1_DATA1_P)
MIPI_CSI1_DATA2_N: J5.B13 U15.BH20(MIPI_CSI1_DATA2_N)
MIPI_CSI1_DATA2_P: J5.B14 U15.BJ21(MIPI_CSI1_DATA2_P)
MIPI_CSI1_DATA3_N: J5.B16 U15.BH12(MIPI_CSI1_DATA3_N)
MIPI_CSI1_DATA3_P: J5.B17 U15.BJ13(MIPI_CSI1_DATA3_P)
MIPI_CSI1_EN: J5.A11 U15.BN13(MIPI_CSI1_GPIO0_01)
MIPI_CSI1_I2C0_SCL: J5.B11 R205.1 U15.BN17(MIPI_CSI1_I2C0_SCL)
MIPI_CSI1_I2C0_SDA: J5.B10 R204.1 U15.BE15(MIPI_CSI1_I2C0_SDA)
MIPI_CSI1_MCLK_OUT: J5.B8 U15.BN23(MIPI_CSI1_MCLK_OUT)
MIPI_CSI1_RST_B: J5.B9 R203.2 U15.BN15(MIPI_CSI1_GPIO0_00)
MIPI_DSI0_1_EN: U15.BD36(LVDS0_I2C0_SDA) ; also on sheet 5
OUT3: C214.1 U29.30(OUT3)
PCIE_WIBT_CLKREQ_B: J12.53(~{CLKREQ0}) R275.1 ; also on sheet 23
PCIE_WIBT_CTRL0_PERST_B: J12.52(~{PERST0}) R273.1 ; also on sheet 23
PCIE_WIBT_CTRL0_WAKE_B: J12.55(~{PEWAKE0}) R272.1 ; also on sheet 23
PCIE_WIBT_REFCLK100M_N: J12.49(REFCLK_N0) ; also on sheet 23
PCIE_WIBT_REFCLK100M_P: J12.47(REFCLK_P0) ; also on sheet 23
PRS_INT1_B: R86.2 R87.2 U21.11(INT1)
PRS_INT2_B: R97.2 R98.2 U21.9(INT2)
PRS_INT_B: R86.1 R93.2 R97.1
PRS_RST: U19.4(Y) U21.16(RST)
PSA_INT1_B: R76.1 R256.2 U14.6(INT1)
PSA_INT2_B: R79.1 R257.2 U14.5(INT2)
PSA_INT_B: R76.2 R79.2 R95.2
RINPUT1: R348.1 U29.5(RINPUT1)
RINPUT2: R333.1 U29.6(RINPUT2)
RINPUT3: R328.1 U29.7(RINPUT3/JD3)
SAI1_MCLK: R245.1 U43.6(Y1)
SAI1_RXD: U29.16(ADCDAT) ; also on sheet 14
SAI1_TXC: U29.12(BCLK) ; also on sheet 14
SAI1_TXD: U29.14(DACDAT) ; also on sheet 14
SAI1_TXFS: U29.13(DACLRC) ; also on sheet 14
SENSORS_INT_B(USDHC2_WP): R107.1 U22.4(Y) ; also on sheet 18
SPK_LN: TP69.1(Pin1) U29.23(SPK_LN)
SPK_LP: TP71.1(Pin1) U29.25(SPK_LP)
SPK_RN: TP61.1(Pin1) U29.19(SPK_RN)
SPK_RP: TP66.1(Pin1) U29.22(SPK_RP)
SUSCLK_32KHZ: J12.50(SUSCLK) U40.13(B1)
SUSCLK_32KHZ(SCU_GPIO0_07): U40.2(A1) ; also on sheet 14
USB_DN: FL5.3 J12.5(USB_D-)
USB_DP: FL5.2 J12.3(USB_D+)
VMID: C209.1 U29.27(VMID)
WIBT_DISABLE_1V8(LVDS1_I2C0_SDA): U15.BE33(LVDS1_I2C0_SDA) U40.3(A2)
WIBT_PCIE0_RX0_N: J12.43(PER_N0) ; also on sheet 23
WIBT_PCIE0_RX0_P: J12.41(PER_P0) ; also on sheet 23
WIBT_PCIE0_TX0_N: J12.37(PET_N0) ; also on sheet 23
WIBT_PCIE0_TX0_P: J12.35(PET_P0) ; also on sheet 23
WIBT_USB_DN: FL5.4 ; also on sheet 22
WIBT_USB_DP: FL5.1 ; also on sheet 22
WIFI_BT_SDIO_CLK: J12.9(SDIO_CLK) ; also on sheet 18
WIFI_BT_SDIO_CMD: J12.11(SDIO_CMD) ; also on sheet 18
WIFI_BT_SDIO_DAT0: J12.13(SDIO_DATA0) ; also on sheet 18
WIFI_BT_SDIO_DAT1: J12.15(SDIO_DATA1) ; also on sheet 18
WIFI_BT_SDIO_DAT2: J12.17(SDIO_DATA2) ; also on sheet 18
WIFI_BT_SDIO_DAT3: J12.19(SDIO_DATA3) ; also on sheet 18
WIFI_DISABLE_B: J12.56(~{W_DISABLE1}) U40.12(B2)
WIFI_EN(WIFI_RST_B): J12.23(~{SDIO_RST}) ; also on sheet 18
WIFI_LED1_B: D7.C(CATHODE) J12.6(~{LED1})
WIFI_WAKE_B(ADC_IN2): J12.21(~{SDIO_WAKE}) ; also on sheet 15
WM89_SAI1__MCLK: R245.2 U29.11(MCLK)
N1440601: R235.2 U15.BJ11(HDMI_RX0_REXT)
N1440696: R236.2 U15.BJ7(HDMI_TX0_REXT)
N16494666: C214.2 TP74.1(Pin1)
N17239595: Q4.3(DRAIN) R34.1 R35.1 R36.1 R37.1 R38.1 R39.1 R45.1 R48.1
N17868331: D2.3(CATHODE1) R50.2
N18555964: R230.1 U40.8(OE)
N18559267: R7.2 U11.5(READY)
N18560075: R4.1 U11.1(ENABLE)
N18560678: R3.2 U16.5(READY)
N18560735: R73.1 U16.1(ENABLE)
N18639770: J3.B8 R211.2
N18639773: J3.B9 R212.2
N18639776: J3.B10 R213.2
N18639779: J3.B11 R214.2
N18639872: J3.A11 R195.2
N18654910: J2.A11 R194.2
N18656239: J2.B8 R206.2
N18656242: J2.B9 R207.2
N18656245: J2.B10 R208.2
N18656248: J2.B11 R209.2
N18672744: R82.1 U20.6(SDA)
N18672747: R83.1 U20.5(SCL)
N18678639: R69.1 U14.8(SCL)
N18678642: R72.1 U14.7(SDA)
N18685002: R93.1 R94.1 R95.1 R96.1 R104.2 U22.1(~{OE})
N18698429: R92.1 U21.4(SCL/SCLK)
N18698432: R100.1 U21.6(SDA/MOSI)
N18715597: C48.2 U13.16(VREGD)
N18720797: R71.1 U13.11(SCL/SCLK)
N18720800: R70.1 U13.12(SDA/MOSI/SPI_DIO)
N18740882: J12.58(I2C_DATA) R268.1
N18740885: J12.60(I2C_CLK) R267.1
N18769875: D7.A(ANODE) R226.1
N18769878: D6.A(ANODE) R225.1
N18774983: C229.2 FB5.1 R180.2
N18890787: D1.3(CATHODE1) R196.2
N22548018: R84.2 U20.3(REXT)
N23062750: J1.17 R199.1
N23062833: C5.1 J1.20 J1.21 J1.22 R8.1
N23063537: J6.17 R217.1
N23063626: C7.1 J6.20 J6.21 J6.22 R9.1

Not connected (* = marked no-connect by the designer): D1 2(NC)*; D2 2(NC)*; J2 A10*; J3 A10*; J5 A10*; J7 A10*; J8 A10*; J10 A10*; J12 38(VEN_DEF1)* 40(VEN_DEF2)* 42(VEN_DEF3)* 44(COEX3)* 46(COEX2)* 48(COEX1)* 59(PET_P1)* 61(PET_N1)* 62(~{ALERT})* 64(RESERVED)* 65(PER_P1)* 66(~{PERST1})* 67(PER_N1)* 68(~{CLKREQ1})* 70(~{PEWAKE1})* 71(REFCLK_P1)* 73(REFCLK_N1)*; U15 BG3(HDMI_TX0_AUX_N)* BL13(HDMI_RX0_ARC_N)*; U19 1(NC)*; U21 15(NC)*; U40 6(NC1)* 9(NC2)*

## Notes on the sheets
sheet 25
- HDMI TX & RX
- ARC_N not used on i.MX8QM
- AUX_N not used on i.MX8QM
- DP: Pulldown unused DDC and CEC pins
  HDMI: DDC requires 2K pullup to 5V
  HDMI: CEC requires 27K pullup to 3V3 with blocking diode
- HPD Pulldown:
  DP 100K
  HDMI 1M
- I/O VOLTAGE :3.3V
- 100-Ohm
  differential
  pairs
sheet 26
- WIFI_BLUETOOTH -M.2 CONNECTOR E-KEY
- Add On Card used will be M.2 with E-Key Type 30x30 Dimension.
- Information on compatible cards is provided on the nxp.com website.
sheet 27
- AUDIO CODEC WM8960
- GPIO1 connected to SCU_GPIO0_03
  of processor
- Headphone Jack pinout changed from OMTP to AHJ on rev C1 schematic and rev C1 layout.
  GND and MIC changed locations to accomodate a wider range of headsets.
- 7-bit I2C Address: "0011010"
sheet 28
- SENSORS
- ACCELEROMETER
- PRESSURE SENSOR WITH ALTIMETRY
- 7-bit I2C Address: 0x60
- I2C ADDRESS CONFIG
  ---------------------------------------------------------
    SA1      SA0     7-bit SLAVE ADDRESS
  -------     ------      ------------------------------------
     0            0       0x1E  (Default)
     0            1       0x1D
     1            0       0x1C
     1            1       0x1F
- SENSOR INTERRUPT
- CONFIGURE ACCELEROMETER,GYROSCOPE,PRESSURE SENSOR
  INTERRUPTS AS OPEN DRAIN,ACTIVE LOW IN RESPECTIVE REGISTERS
- GYROSCOPE
- AMBIENT LIGHT SENSOR
- 7-bit I2C Address: 0x44
- I2C ADDRESS CONFIG
  ----------------------------------------------
    SA0      7-bit SLAVE ADDRESS
  -------     ----------------------------------
     0        0x20 (Default)
     1        0x21
sheet 29
- LVDS0 CH0 & CH1 CONNECTORS
- 100-Ohm
  differential
  pairs
- 100-Ohm
  differential
  pairs
- 100-Ohm
  differential
  pairs
- 100-Ohm
  differential
  pairs
sheet 30
- MIPI CSI CONNECTORS
- 100-Ohm
  differential
  pairs
- 100-Ohm
  differential
  pairs
sheet 31
- MCLK CLOCK DRIVERS FOR BASE BOARD FAN OUT
- LEVEL TRANSLATOR
- I2C BUFFERS FOR BASE BOARD
- ETHERNET TX  BUFFERS FOR BASEBOARD
